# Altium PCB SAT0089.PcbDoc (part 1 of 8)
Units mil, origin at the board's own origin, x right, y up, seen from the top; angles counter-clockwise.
Board outline 4075 x 2715 mil, 6 copper layers (Top Layer, InternalPlane1, MidLayer1, Internal Plane 3, InternalPlane2, Bottom Layer), stack 67.4 mil thick; 538 components, 405 nets, 1716 pads, 1236 vias.
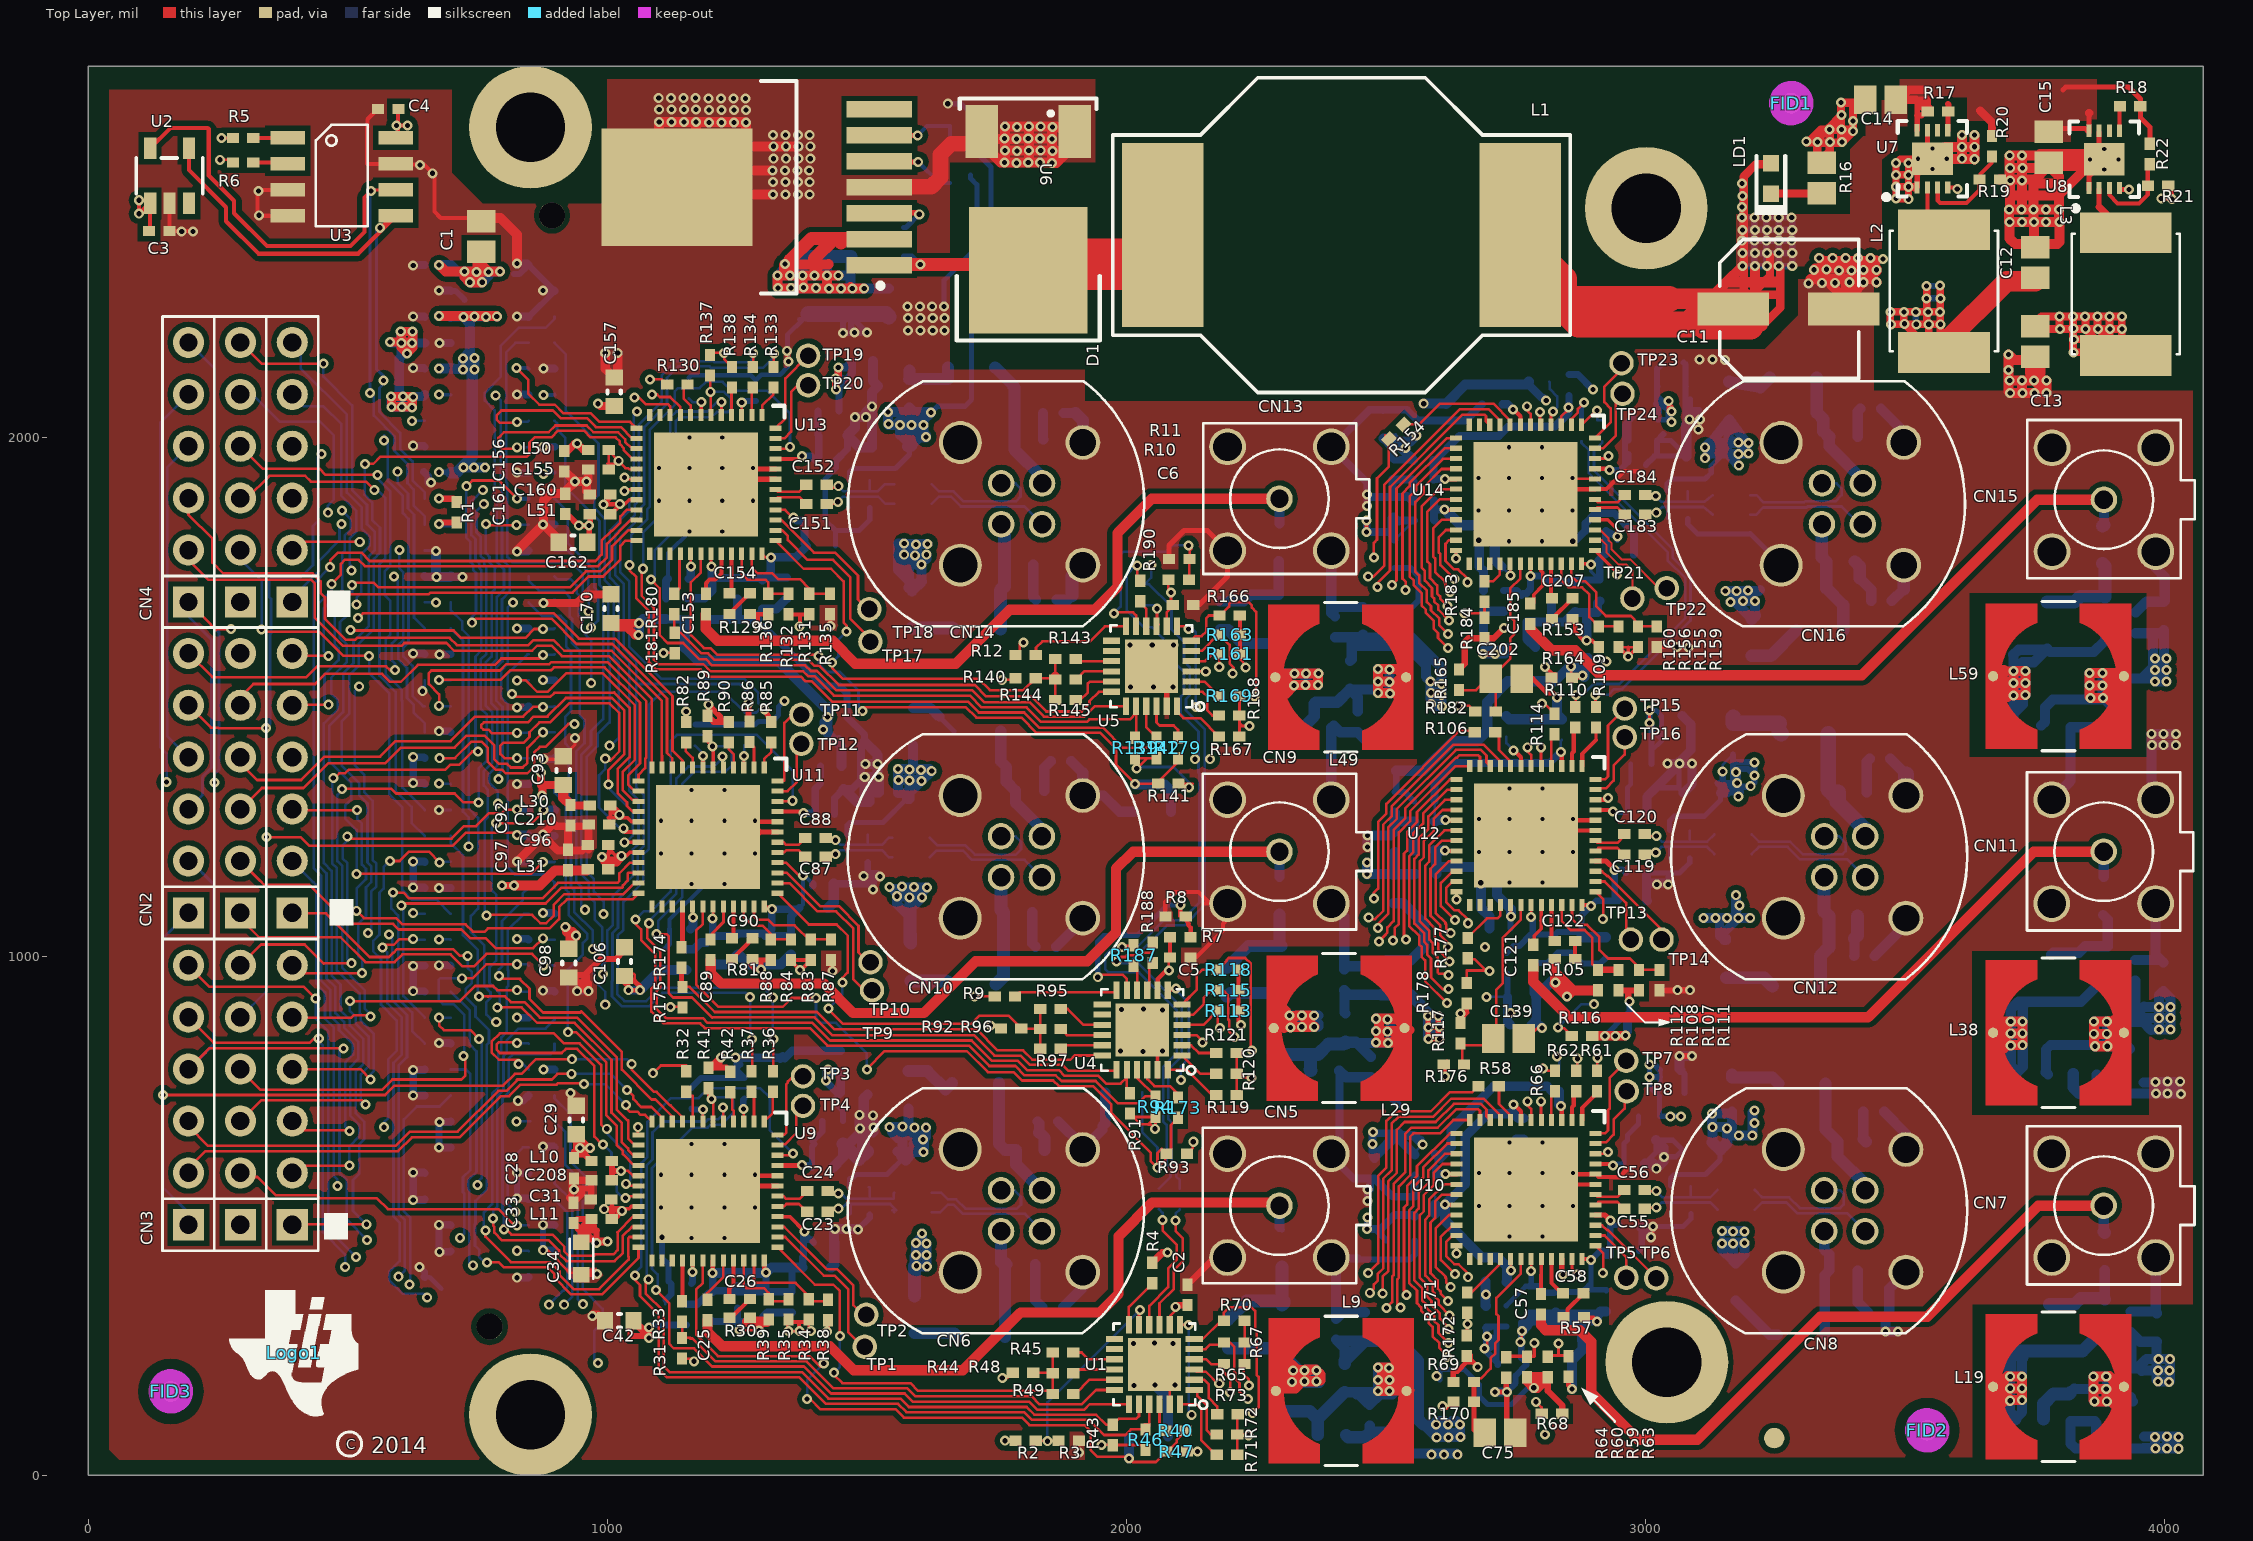
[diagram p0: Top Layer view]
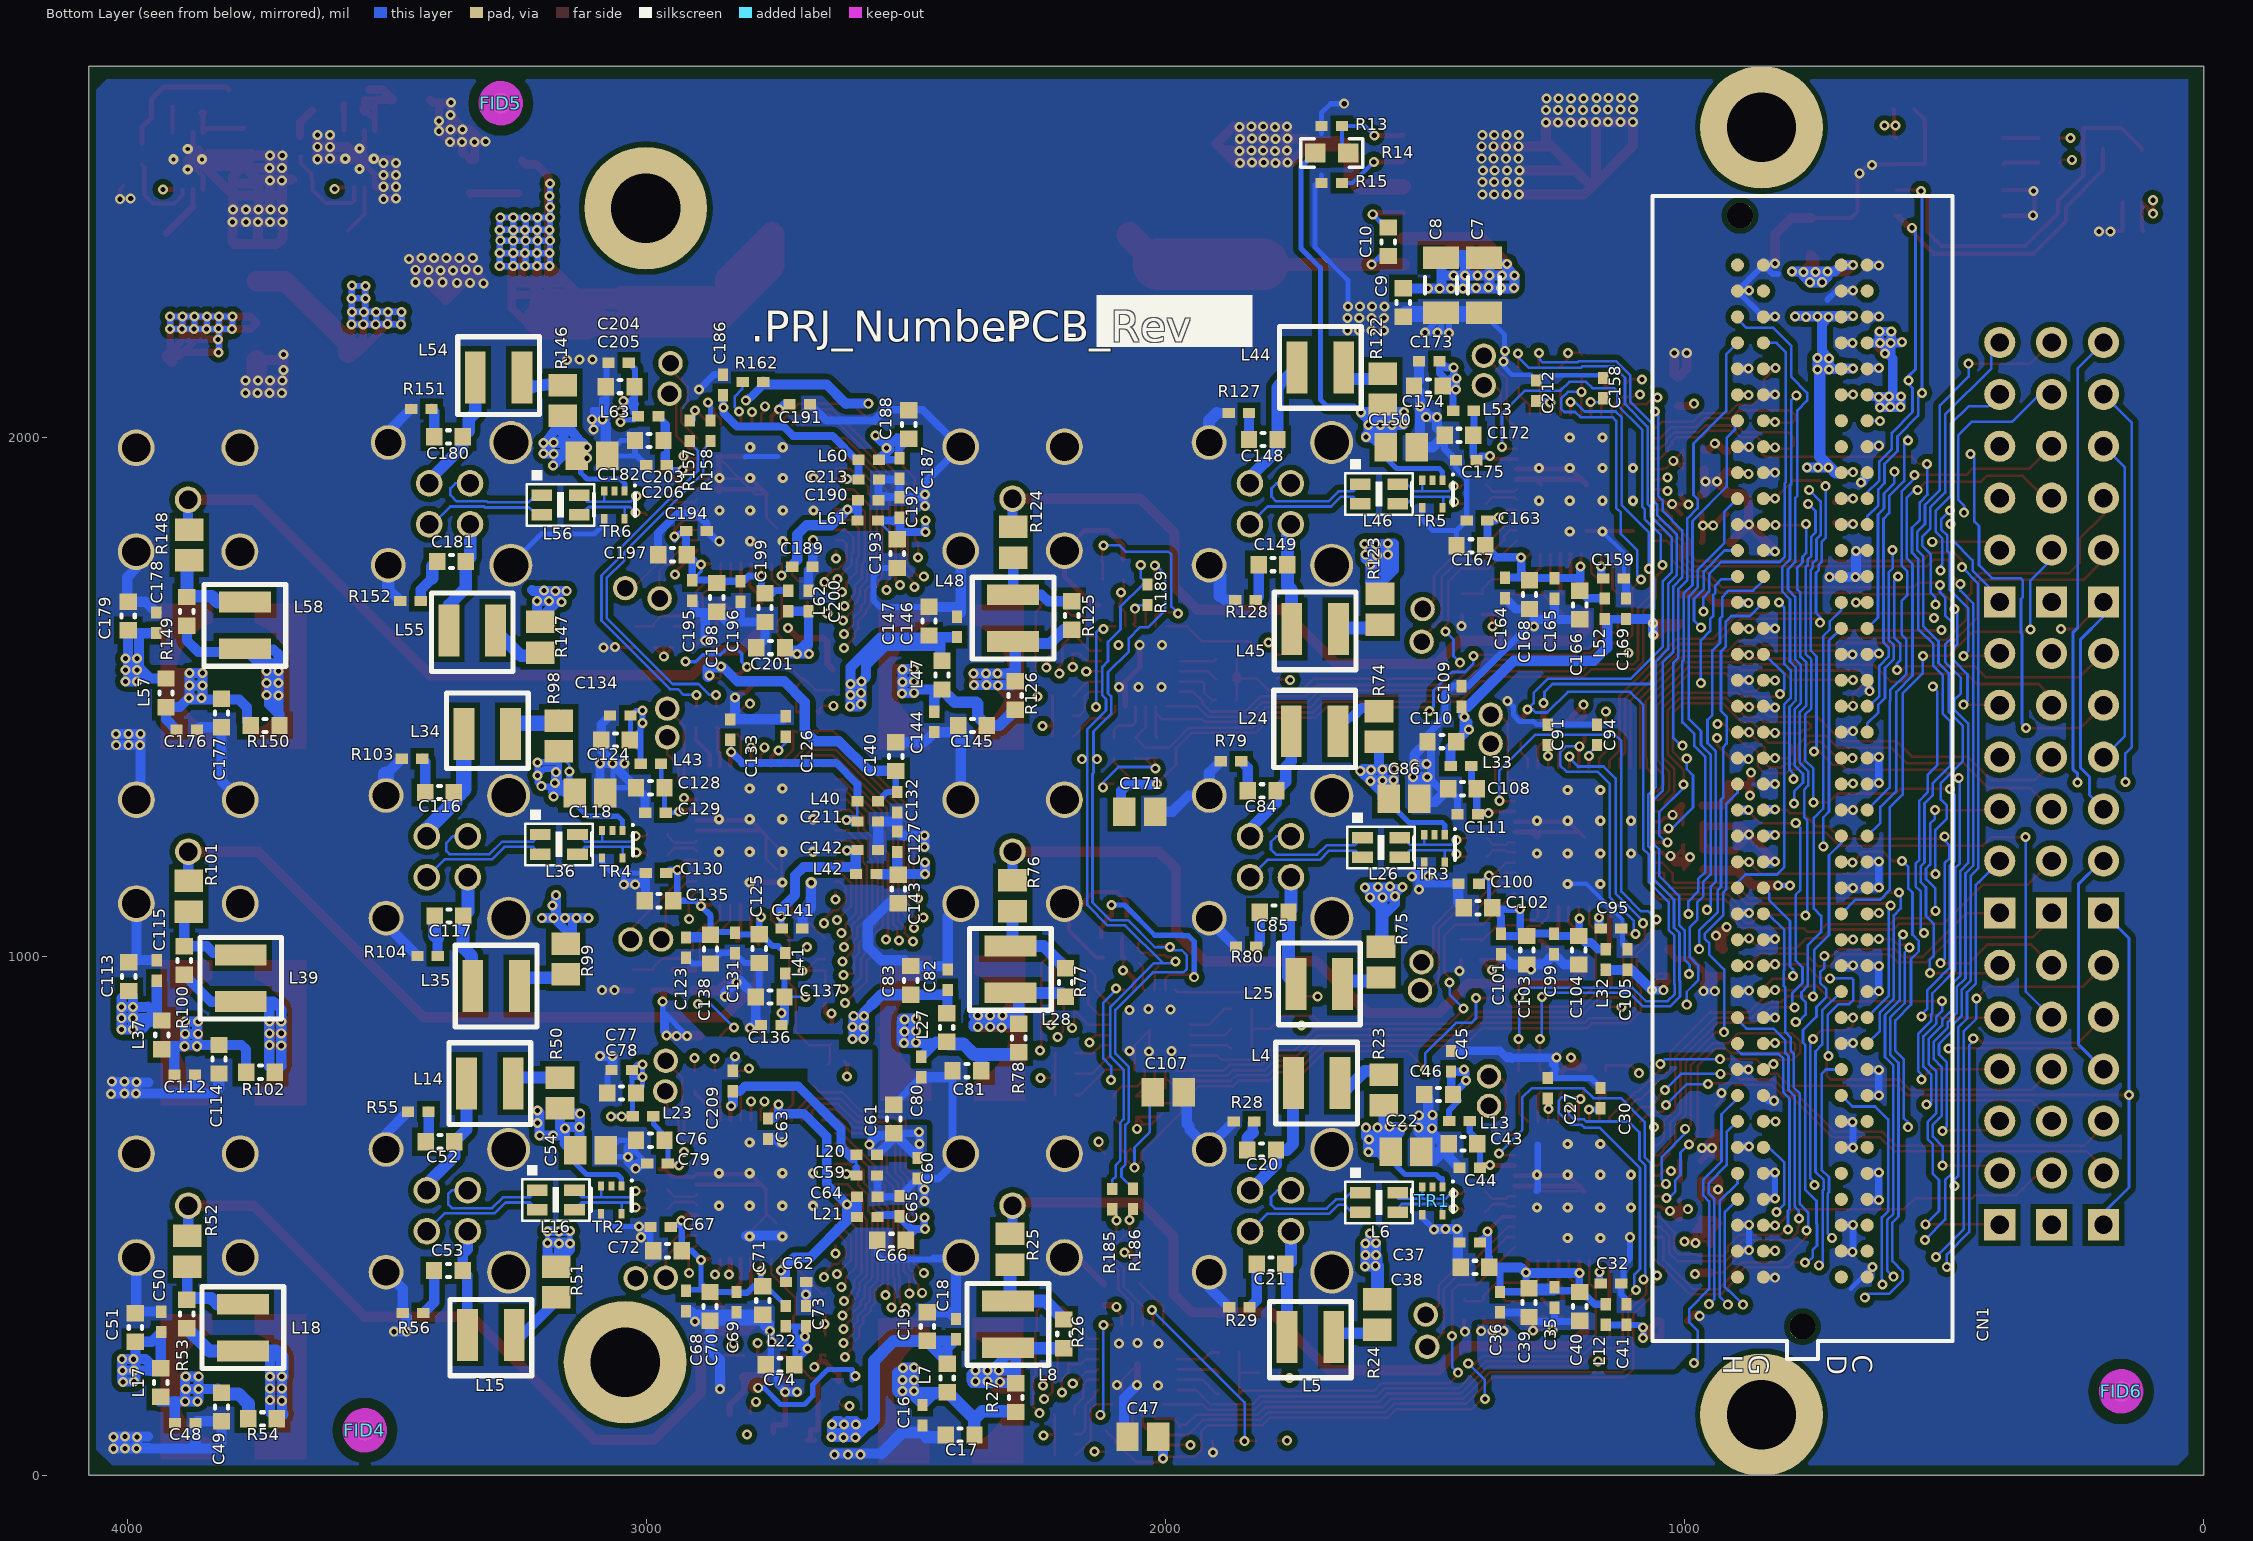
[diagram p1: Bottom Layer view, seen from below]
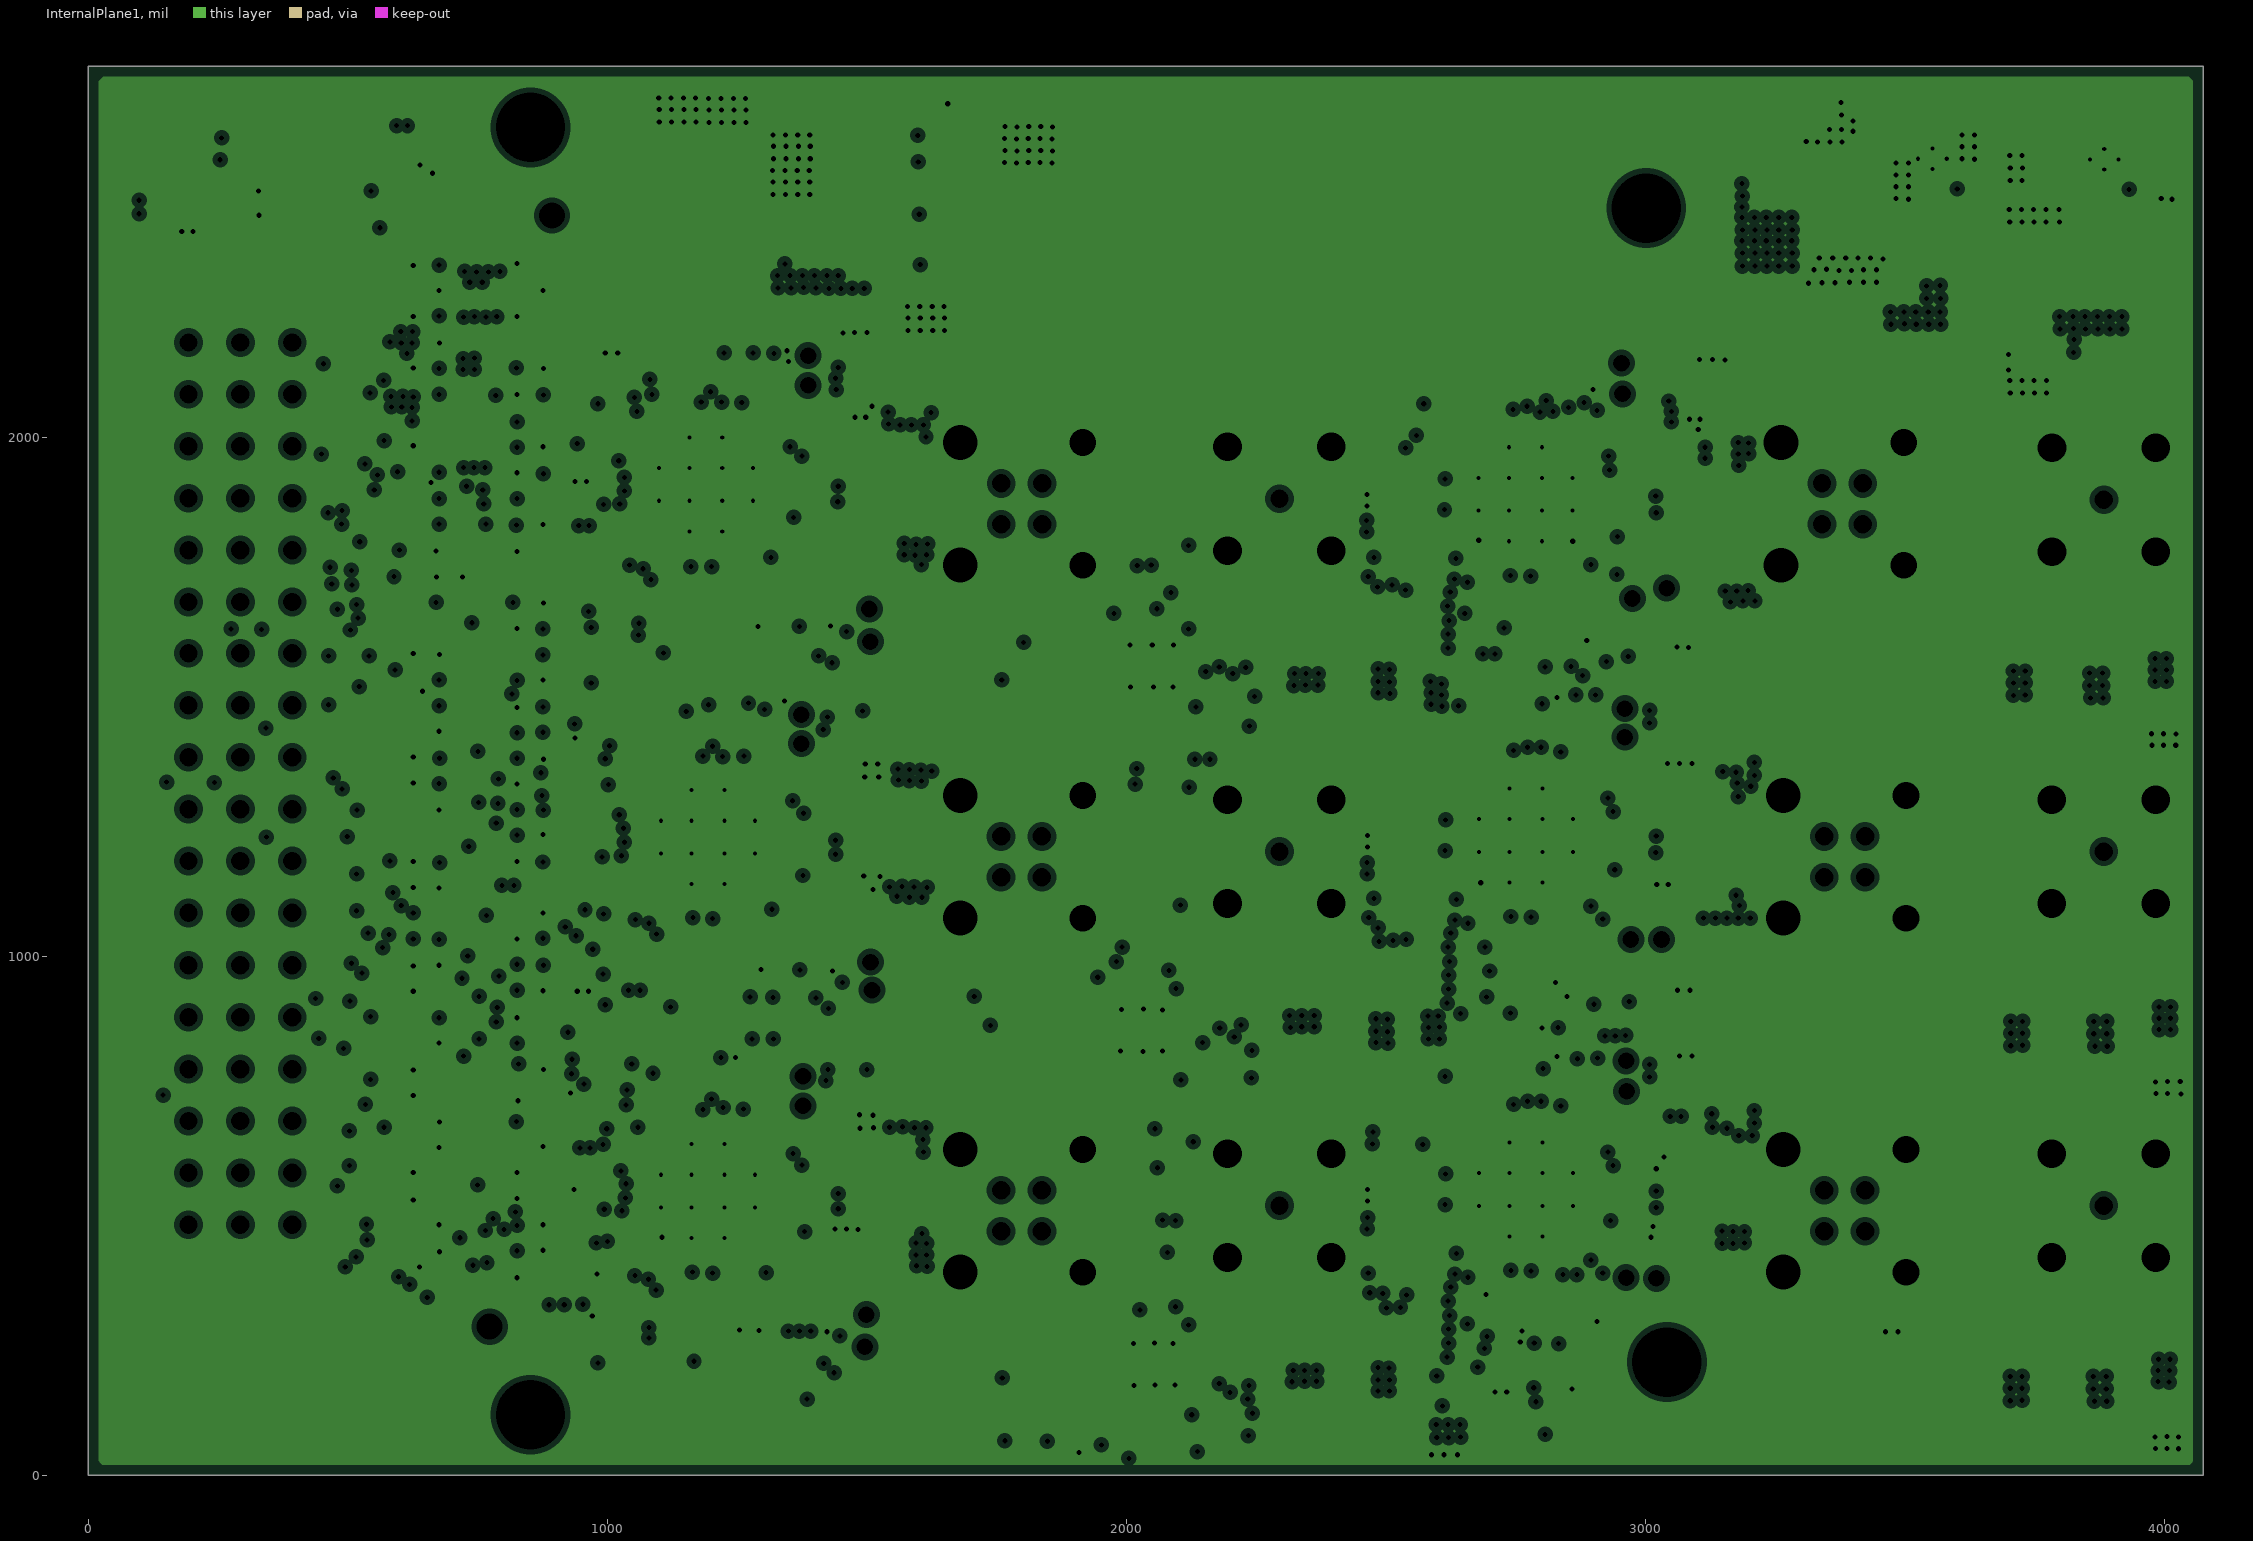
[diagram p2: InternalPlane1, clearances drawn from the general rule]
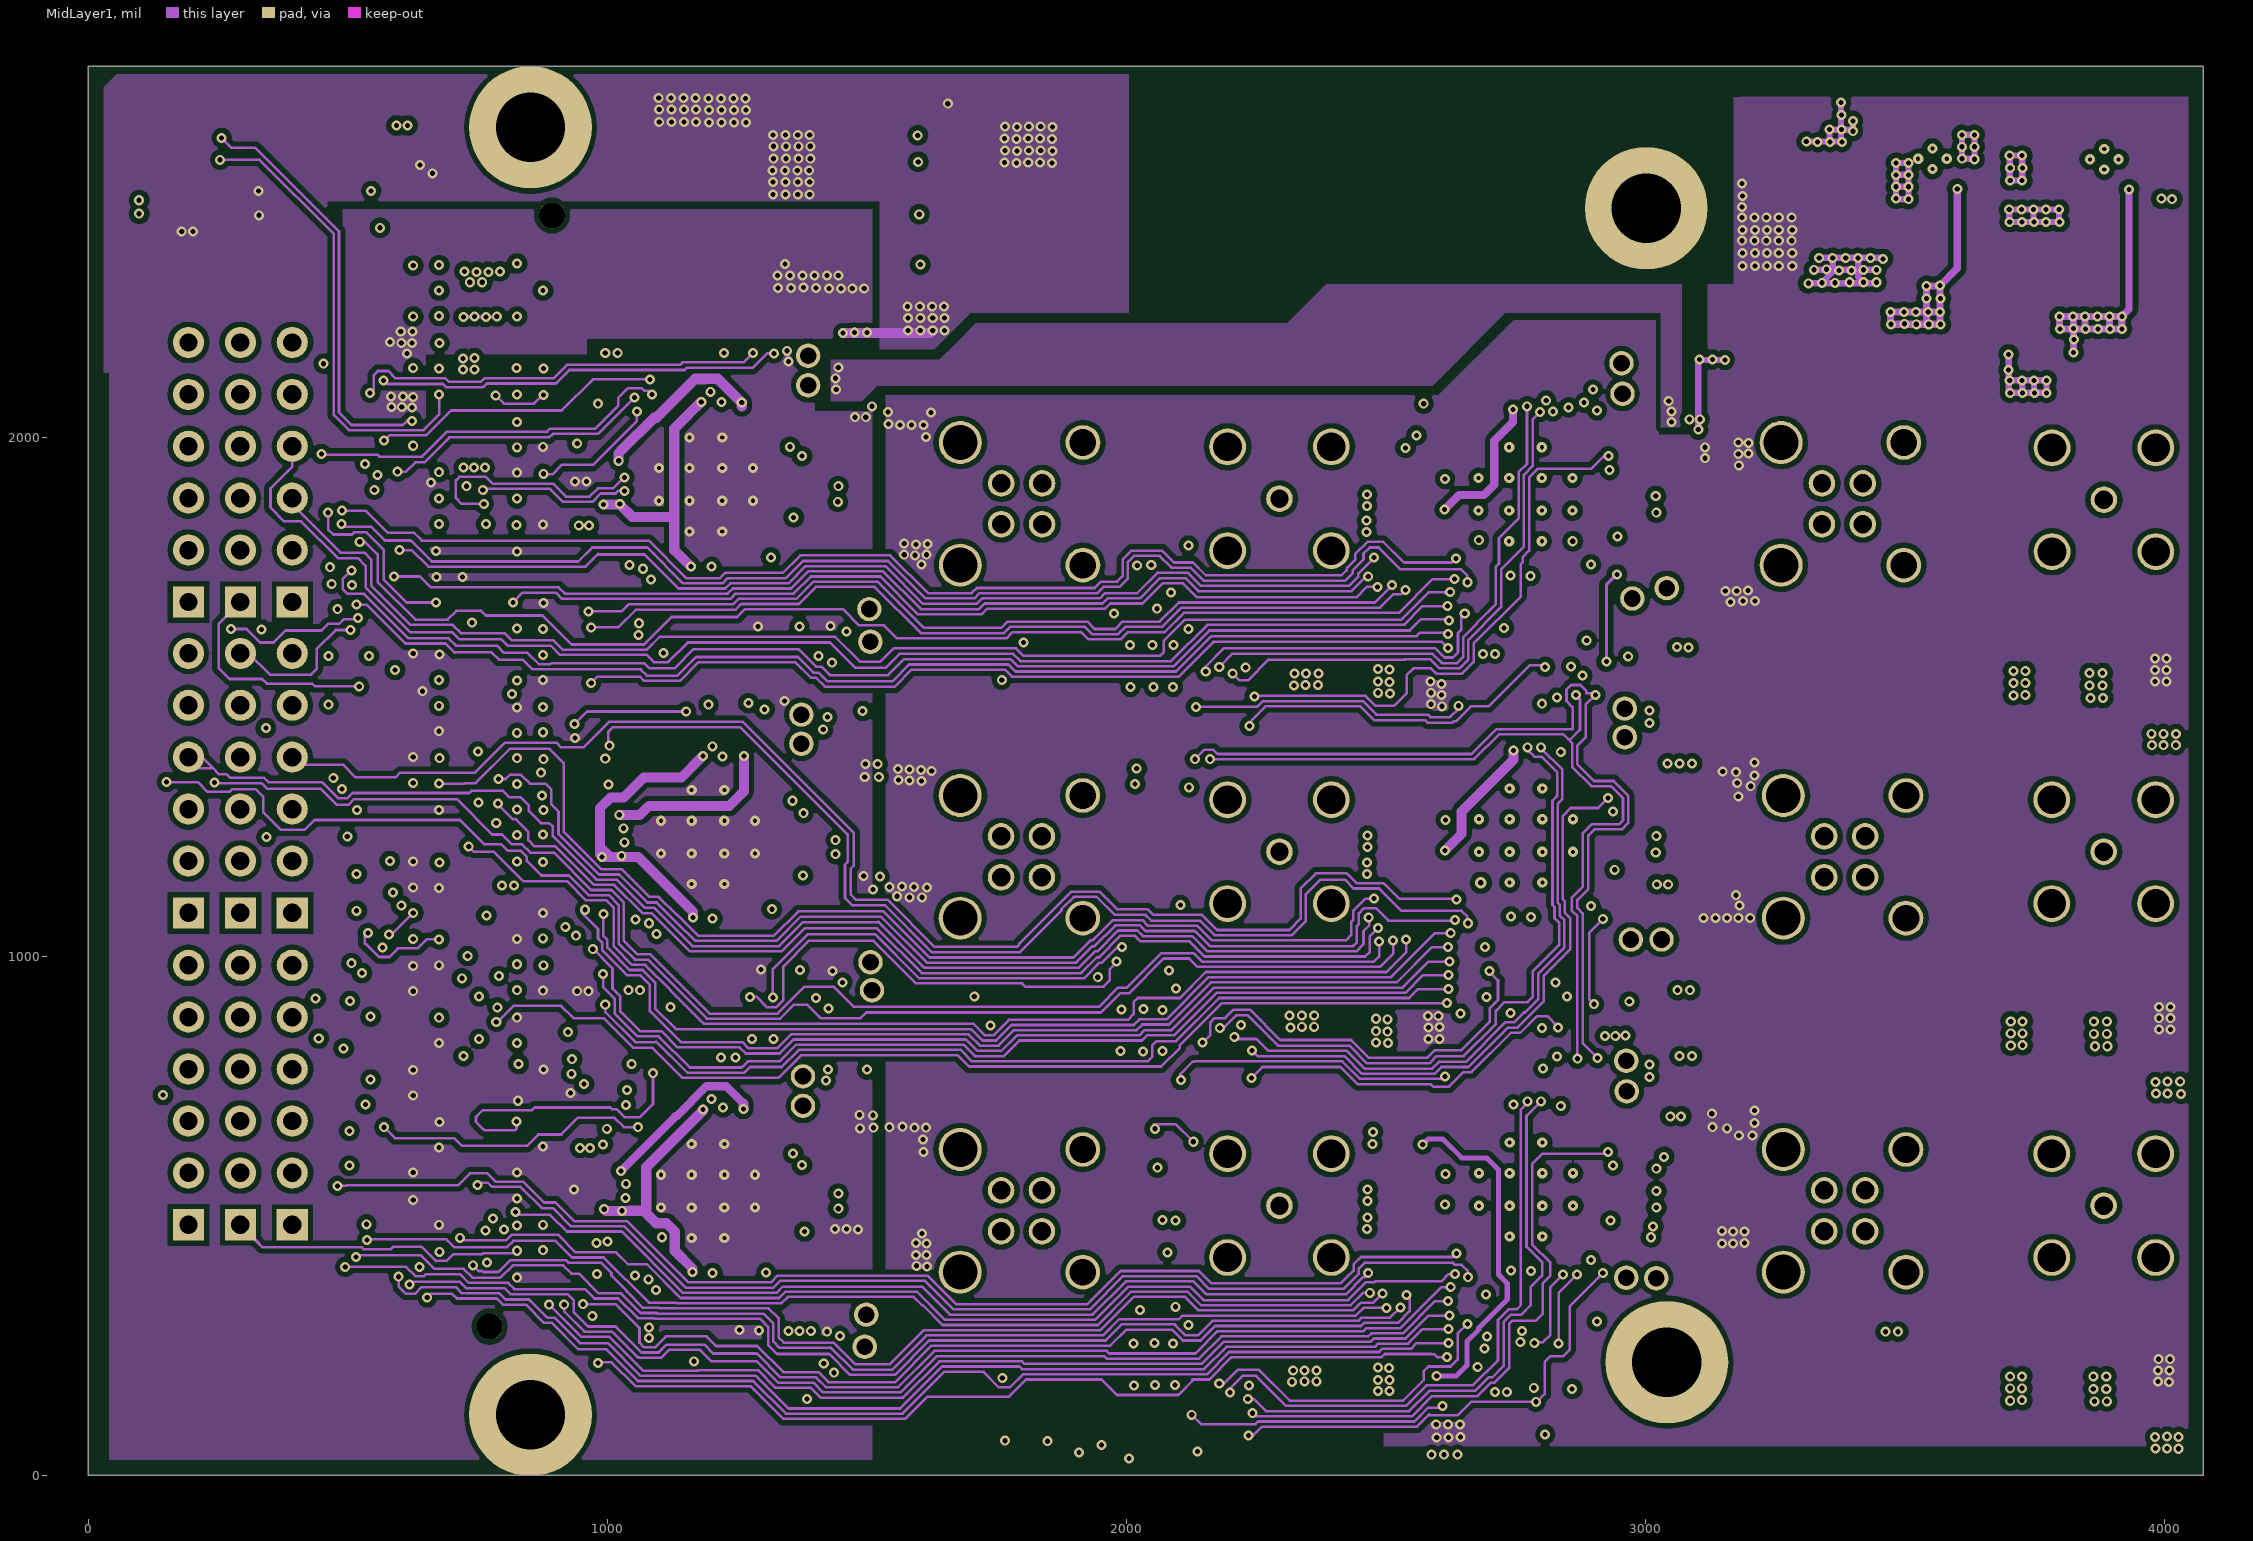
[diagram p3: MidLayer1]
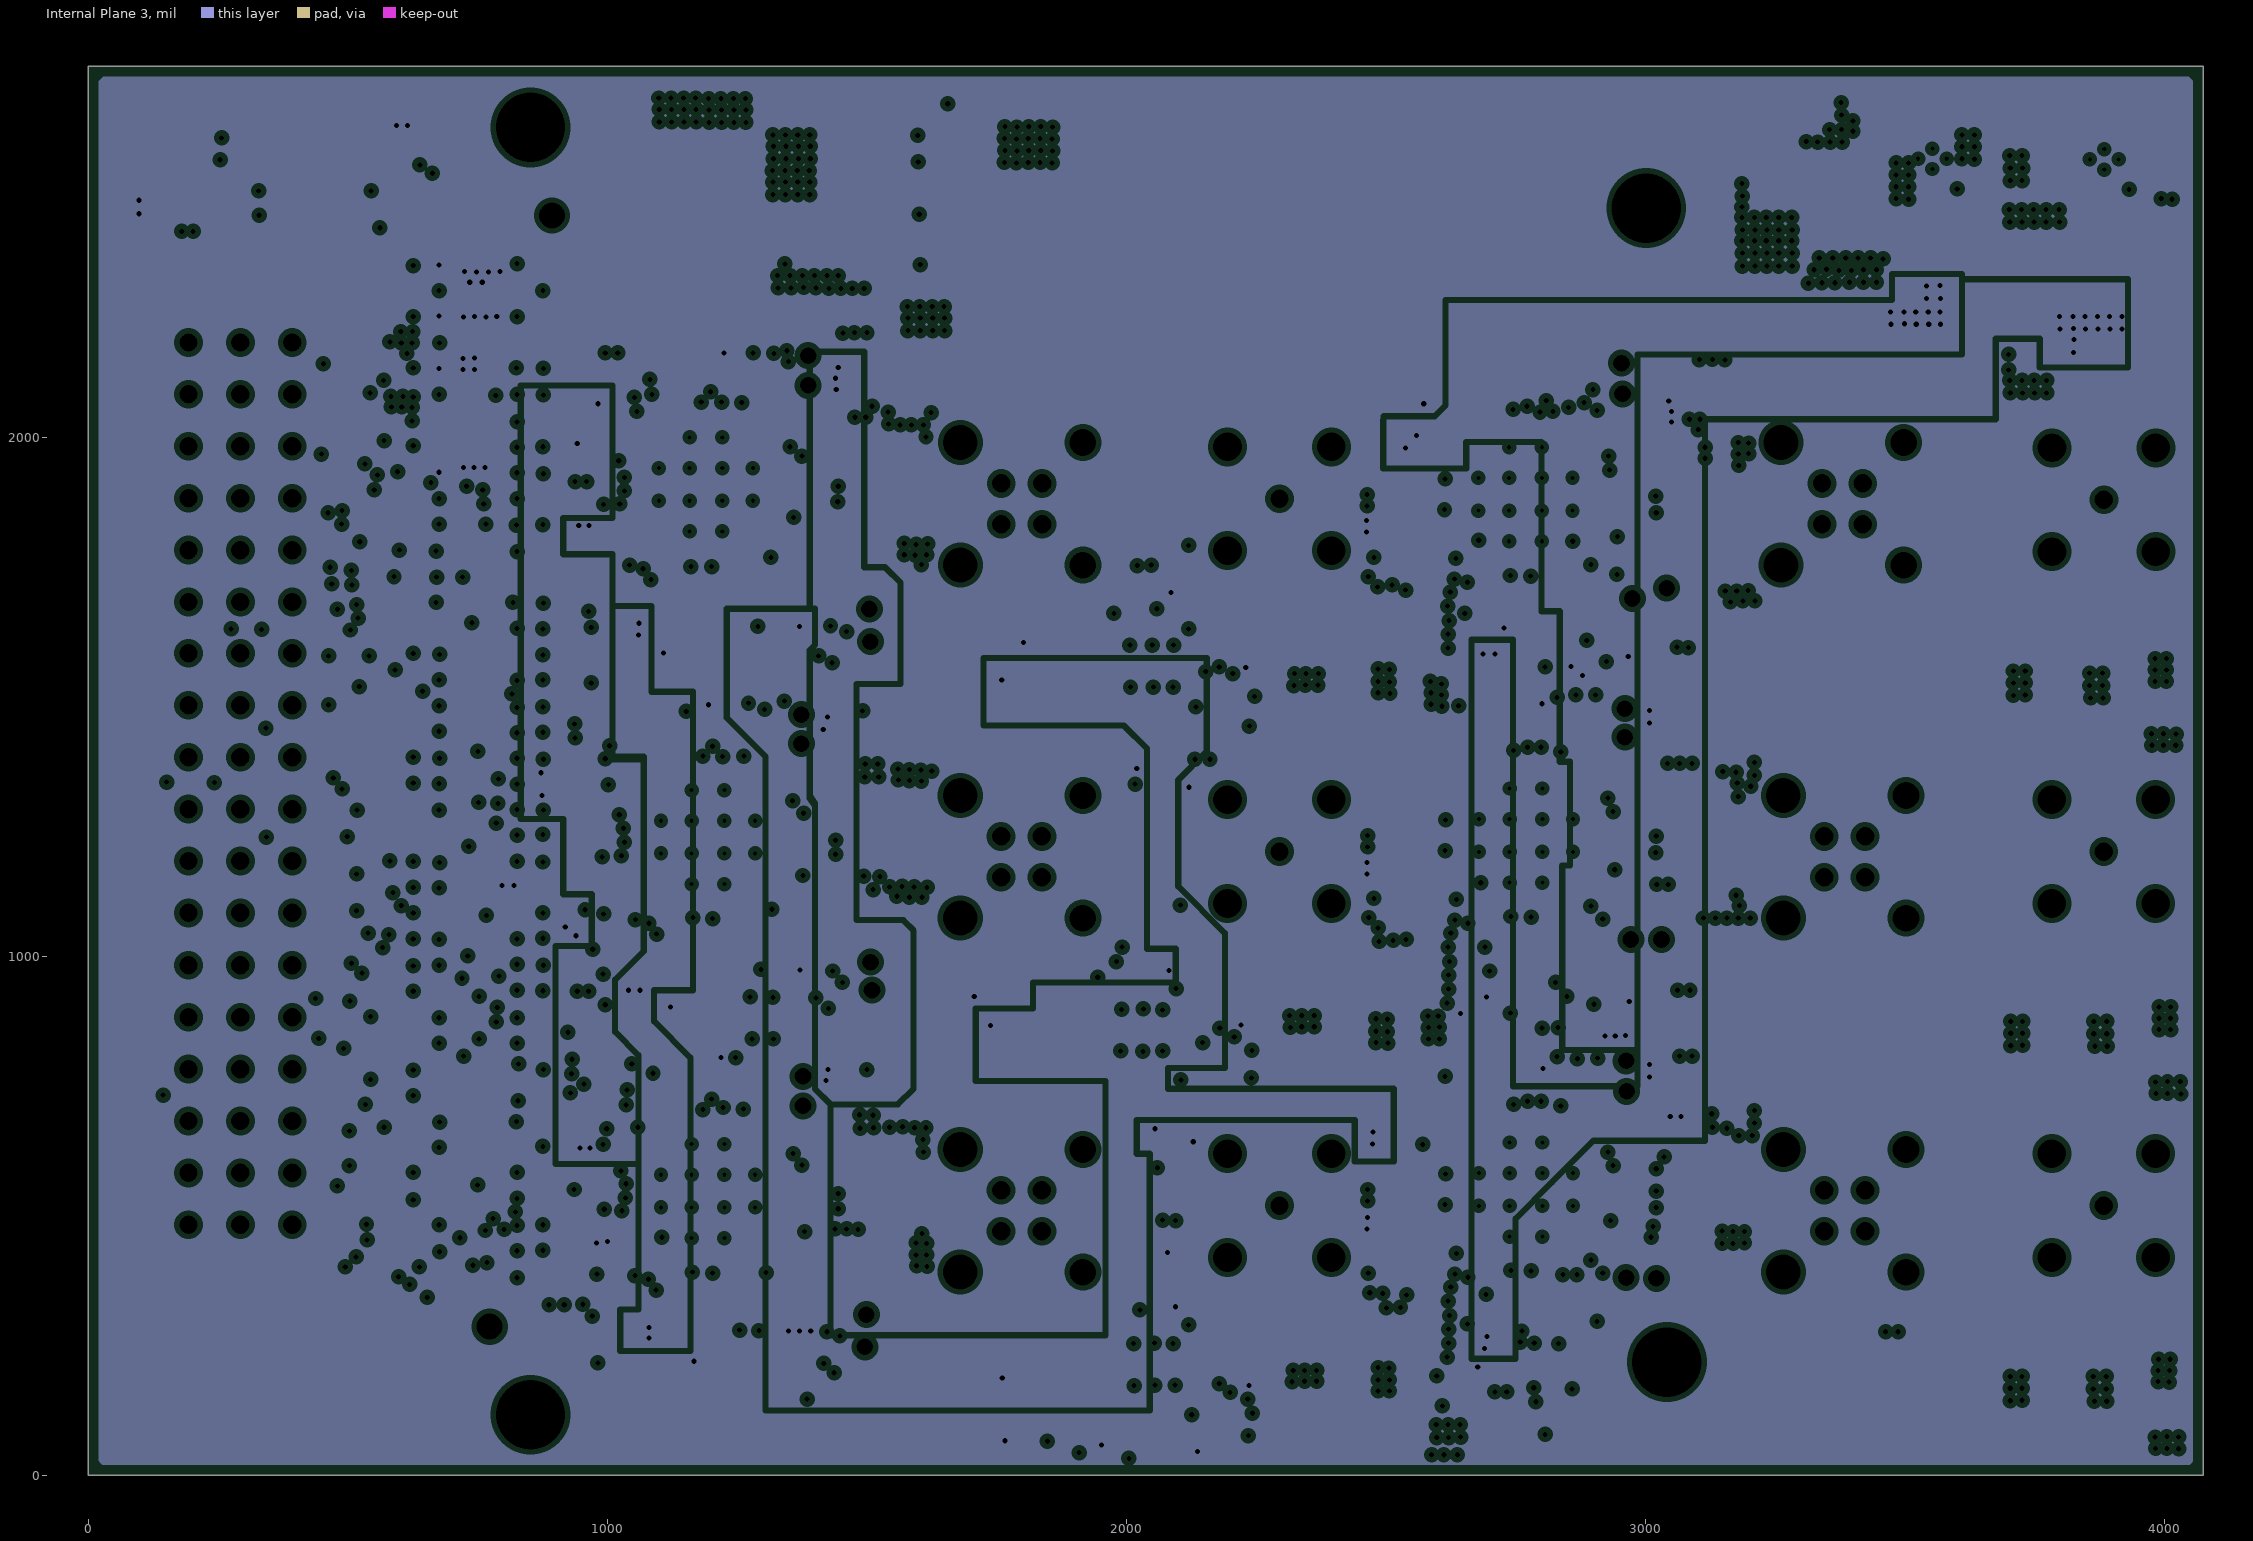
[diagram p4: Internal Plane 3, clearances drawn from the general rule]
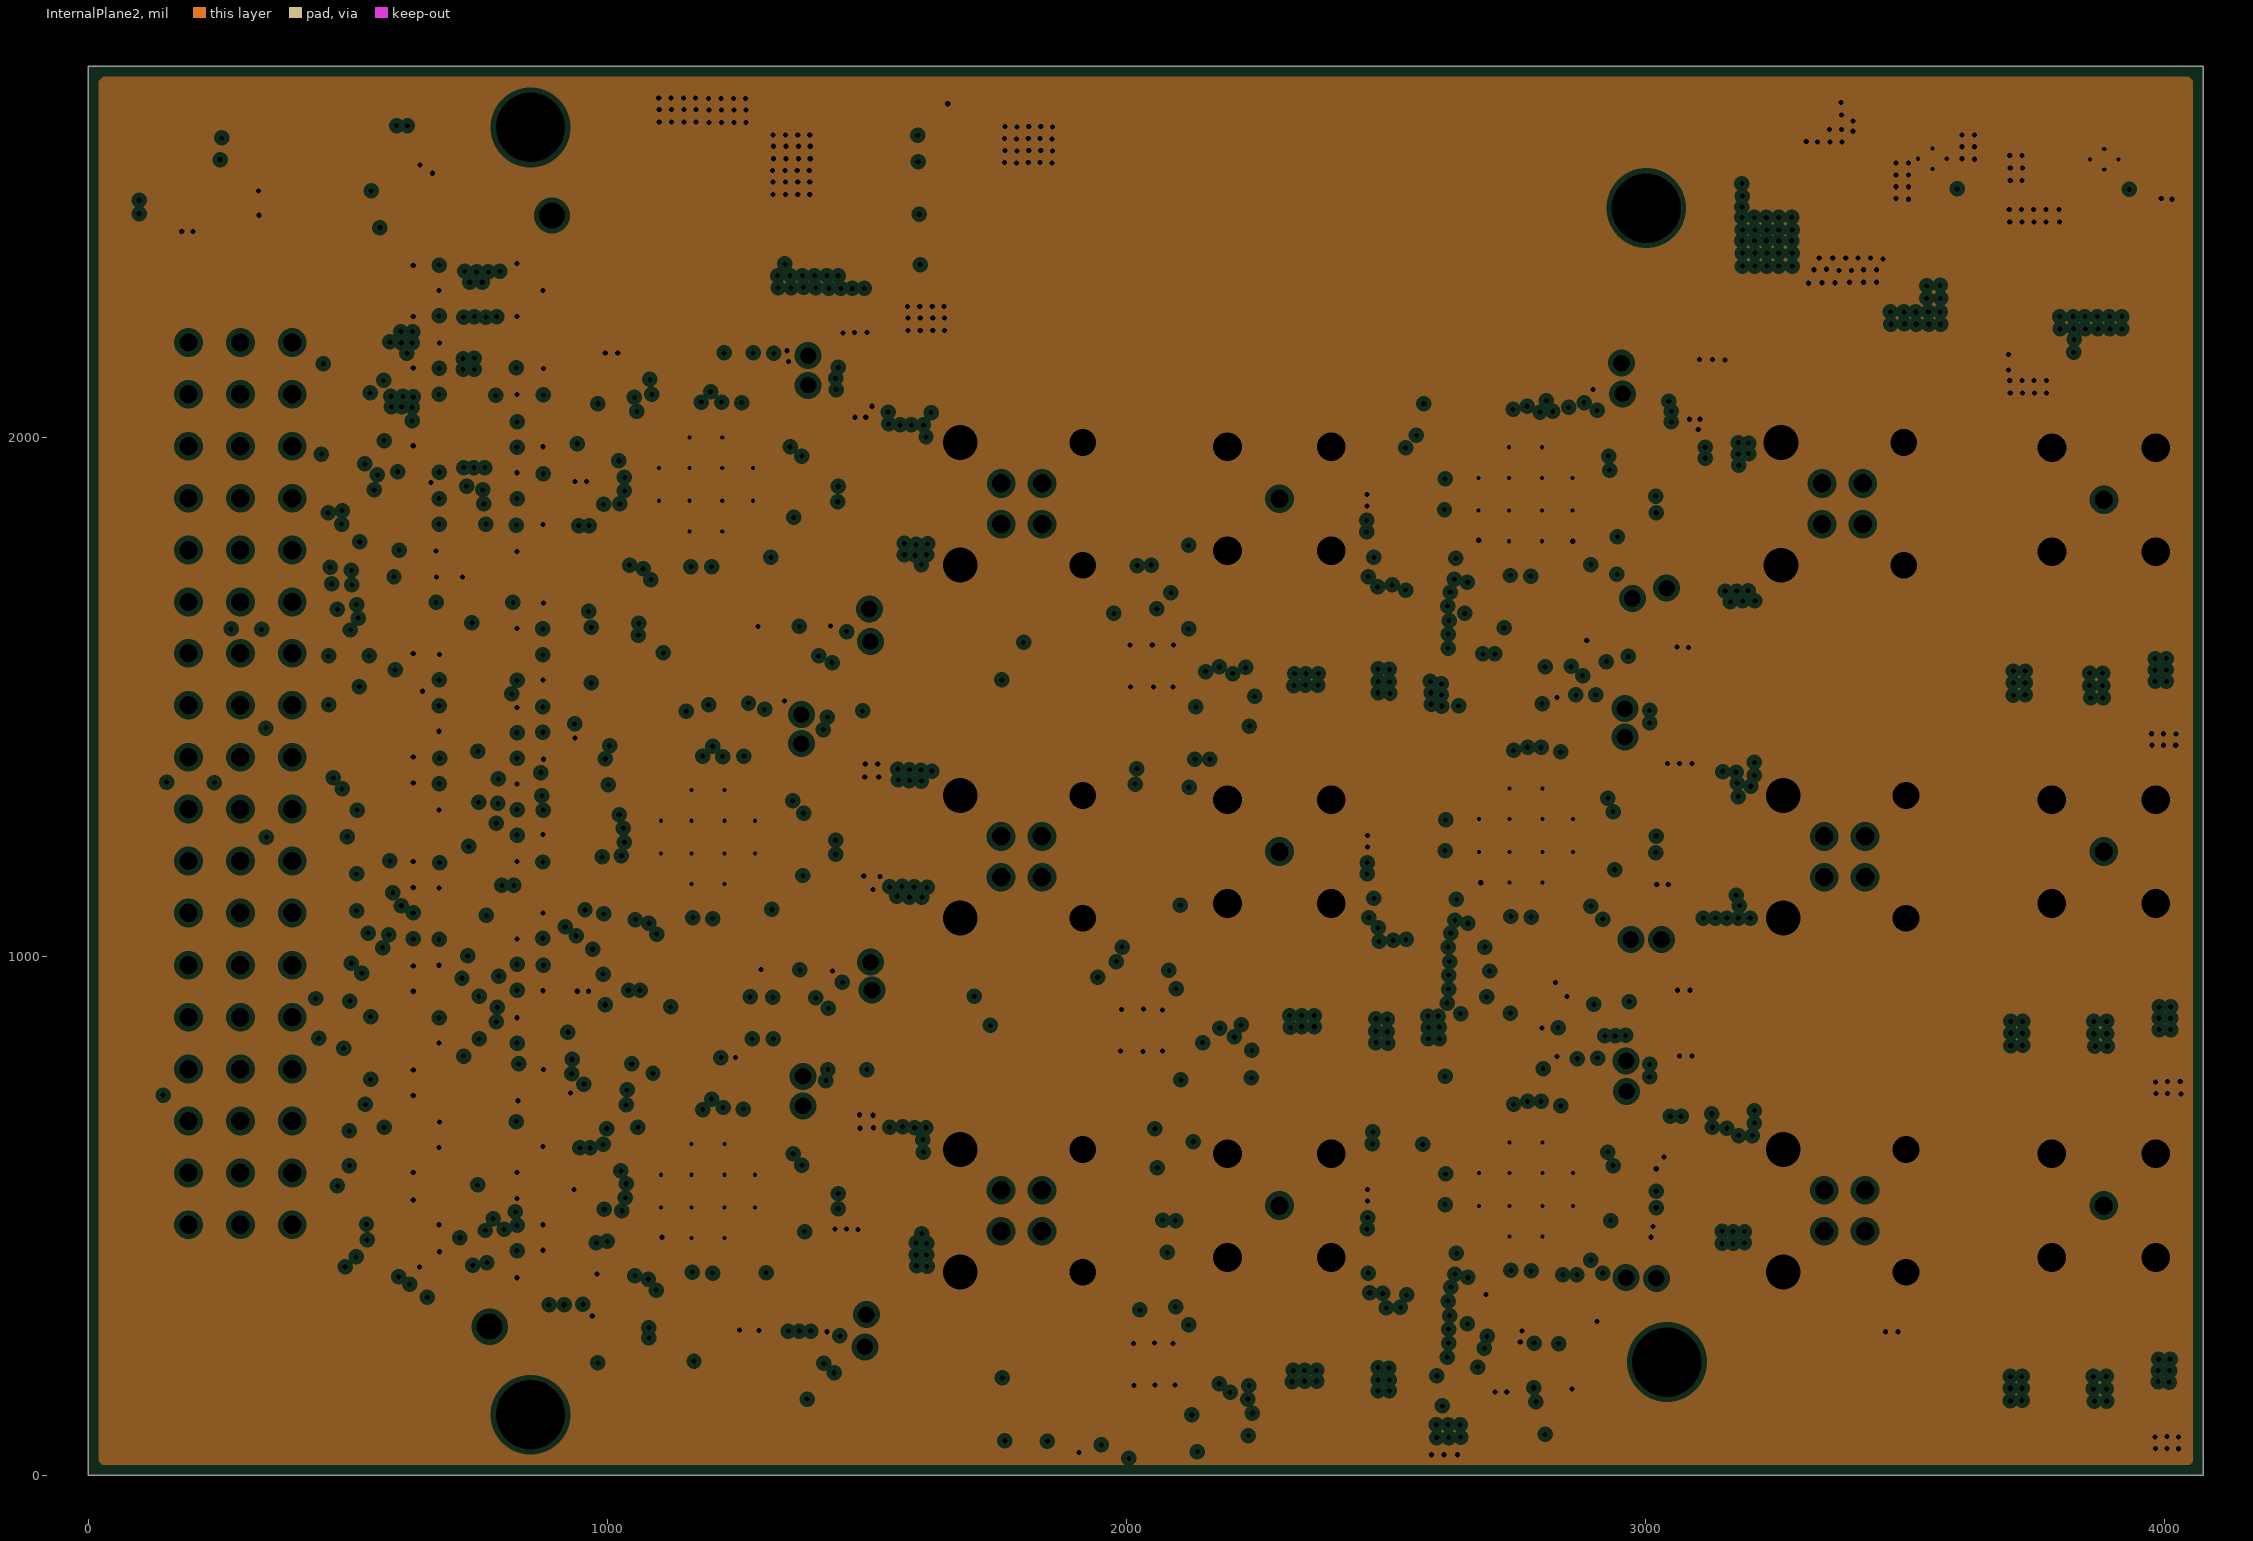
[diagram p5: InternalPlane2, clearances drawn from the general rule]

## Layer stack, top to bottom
Top Layer: signal copper 1.4
Dielectric: prepreg 13, 370HR, Dk 4.8
InternalPlane1: plane copper 1.4, net DGND
Dielectric: core 10, 370HR, Dk 4.8
MidLayer1: signal copper 1.4
Dielectric: prepreg 13, 370HR, Dk 4.8
Internal Plane 3: plane copper 1.4, net (Multiple Nets)
Dielectric: core 10, 370HR, Dk 4.8
InternalPlane2: plane copper 1.4, net DGND
Dielectric: prepreg 13, 370HR, Dk 4.8
Bottom Layer: signal copper 1.4

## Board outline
0,0 0,2715 4075,2715 4075,0

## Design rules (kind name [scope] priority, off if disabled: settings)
AcuteAngle [All] p1: minimum=4.50000000000000E+0001 checktracksonly=FALSE
AssemblyTestPointUsage [All] p1: valid=2
Clearance Clearance_BoardEdge_MountingHoles [OnCopper and InComponentClass('Mounting Holes') vs IsKeepOut] p1: gap=30
Clearance Clearance_BoardEdge_Poly [OnCopper and InPoly vs IsKeepOut] p2: gap=20
Clearance Clearance_BoardEdge [OnCopper and Not InComponentClass('Logo') and not InComponentClass('FiducialMark') and not InRegion(1000,500,4000,800) and Not IsKeepout vs IsKeepOut] p3: gap=20
Clearance Clearance_Poly [InPolygon] p4: gap=10
Clearance [All] p5: gap=5
ComponentClearance ComponentClearance_Shunt [InComponentClass('Header') vs InComponentClass('Shunt')] p1 off: gap=0 collisioncheckmode=3 verticalgap=0 showdistances=FALSE
ComponentClearance ComponentClearance_Logo [InComponentClass('Logo')] p2 off: gap=50 collisioncheckmode=3 verticalgap=10 showdistances=FALSE
ComponentClearance ComponentClearance_ScrewToNut [(HasFootprint('NY PMS 440 0025 PH')) vs (HasFootprint('Keystone_1902C'))] p3 off: gap=5 collisioncheckmode=3 verticalgap=10 showdistances=FALSE
ComponentClearance ComponentClearance_MountingHoles [InComponentClass('Mounting Holes')] p4 off: gap=250 collisioncheckmode=3 verticalgap=100000 showdistances=FALSE
ComponentClearance ComponentClearance_SmallPassives [HasFootprint('0201*') or HasFootprint('0402*') or HasFootprint('0508') or HasFootprint('0603*') or HasFootprint('0612') or HasFootprint('0805*') or HasFootprint('0815*') or HasFootprint('0830*') or HasFootprint('1206*') or HasFootprint('1210*') or HasFootprint('1808*') or HasFootprint('1812*') or HasFootprint('1825*') or HasFootprint('2010*') or HasFootprint('2220*') or HasFootprint('2225*') or HasFootprint('2512*') or HasFootprint('2728*') or HasFootprint('3518*') vs HasFootprint('0201*') or HasFootprint('0402*') or HasFootprint('0508') or HasFootprint('0603*') or HasFootprint('0612') or HasFootprint('0805*') or HasFootprint('0815*') or HasFootprint('0830*') or HasFootprint('1206*') or HasFootprint('1210*') or HasFootprint('1808*') or HasFootprint('1812*') or HasFootprint('1825*') or HasFootprint('2010*') or HasFootprint('2220*') or HasFootprint('2225*') or HasFootprint('2512*') or HasFootprint('2728*') or HasFootprint('3518*')] p5 off: gap=20 collisioncheckmode=3 verticalgap=10 showdistances=FALSE
ComponentClearance ComponentClearance_THtoSMT [IsThruComponent vs IsSMTComponent] p6 off: gap=100 collisioncheckmode=3 verticalgap=30 showdistances=FALSE
ComponentClearance ComponentClearance_THtoTH [IsThruComponent vs IsThruComponent] p7 off: gap=118.11 collisioncheckmode=3 verticalgap=30 showdistances=FALSE
ComponentClearance [All] p8 off: gap=40 collisioncheckmode=3 verticalgap=10 showdistances=FALSE
DiffPairsRouting [All] p1: maxlimit=100 minlimit=10 mostfreqgap=10 maxuncoupledlength=1000
FabricationTestPointUsage TestPointUsage [All] p1: valid=2 allowmultiple=FALSE
FabricationTestpoint Testpoint [All] p1: side=3 testpointundercomponent=TRUE minsize=40 maxsize=100 preferedsize=60 minholesize=0 maxholesize=40 preferedholesize=32 testpointgrid=1 allowsidetop=TRUE allowsidebottom=TRUE usegrid=TRUE gridtolerance=0.01
FanoutControl Fanout_LCC [IsLCC] p1: bgadir=Out bgaviamode=Centered fanoutstyle=Auto fanoutdirection=Alternating viagrid=1 // Fanout_LCC (Default Rule)
FanoutControl Fanout_BGA [IsBGA] p2: bgadir=Out bgaviamode=Centered fanoutstyle=Auto fanoutdirection=Alternating viagrid=1 // Fanout_BGA (Default Rule)
FanoutControl Fanout_Default [All] p4: bgadir=Out bgaviamode=Centered fanoutstyle=Auto fanoutdirection=Alternating viagrid=1 // Fanout_Default (Default Rule)
FanoutControl Fanout_Small [(CompPinCount < 5)] p5: bgadir=Out bgaviamode=Centered fanoutstyle=Auto fanoutdirection=OutThenIn viagrid=1 // Fanout_Small (Default Rule)
HoleSize [All] p1: absolutevalues=TRUE maxlimit=251 minlimit=7.8 maxpercent=80.000 minpercent=20.000
MinimumAnnularRing MinimumAnnularRing_ThermalPadVias [IsVia and InAnyComponent] p1: minimumring=5.91
MinimumAnnularRing [All] p2: minimumring=4.7
MinimumSolderMaskSliver MinimumSolderMaskSliver_Logo [InComponentClass('Logo') vs InComponentClass('Logo')] p1: minsoldermaskwidth=0.7
MinimumSolderMaskSliver [All] p2: minsoldermaskwidth=4
PlaneClearance [All] p1: clearance=10
PlaneConnect [All] p1: planeconnectstyle=Direct reliefexpansion=10 reliefentries=4 reliefconductorwidth=10 reliefairgap=10
PolygonConnect [All] p1: connectstyle=Direct reliefconductorwidth=10 reliefentries=4 polygonreliefangle="90 Angle" airgapwidth=10
RoutingVias ThermalPadVias [IsVia and InAnyComponent] p1: holewidth=7.87 width=19.68 viastyle="Through Hole" minholewidth=7.87 minwidth=19.68 maxholewidth=12.99 maxwidth=23.62
RoutingVias [All] p2: holewidth=16 width=34 viastyle="Through Hole" minholewidth=7.87 minwidth=19 maxholewidth=40 maxwidth=65
SMDToCorner [All] p1: distance=30000
SilkToSilkClearance [All] p1 off: silktosilkclearance=5
SilkscreenOverComponentPads [All] p1: minsilkscreentomaskgap=0.2
SolderMaskExpansion [All] p1: expansion=1
Width [All] p1: maxlimit=100 minlimit=4 preferedwidth=10 midlayer1_minwidth=5 bottomlayer_minwidth=5 minimp=50.000000 maximp=50.000000 favimp=50.000000 checkconnectedcopper=TRUE
13 further rules are at their usual default settings.

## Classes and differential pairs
component class Logo: Logo1
component class Hardware_ANSI-B: FID1 FID2 FID3 FID4 FID5 FID6 Logo1 ZZ2 ZZ3 ZZ4
component class FiducialMark: FID1 FID2 FID3 FID4 FID5 FID6
component class AssemblyNote: ZZ2 ZZ3 ZZ4
component class "CAMERA 1": C16 C17 C18 C19 C20 C21 C22 C23 C24 C25 C26 C27 C28 C29 C30 C31 C32 C33 C34 C35 C36 C37 C38 C39 C40 C41 C42 C43 C44 C45 C46 C47 C208 CN5 CN6 L4 L5 L6 L7 L8 L9 L10 L11 L12 L13 R23 R24 R25 R26 R27 R28 R29 R30 R31 R32 R33 R34 R35 R36 R37 R38 R39 R40 R41 R42 R43 R44 R45 R46 R47 R48 R49 TP1 TP2 TP3 TP4 TR1 U9
component class "CAMERA 2": C48 C49 C50 C51 C52 C53 C54 C55 C56 C57 C58 C59 C60 C61 C62 C63 C64 C65 C66 C67 C68 C69 C70 C71 C72 C73 C74 C75 C76 C77 C78 C79 C209 CN7 CN8 L14 L15 L16 L17 L18 L19 L20 L21 L22 L23 R50 R51 R52 R53 R54 R55 R56 R57 R58 R59 R60 R61 R62 R63 R64 R65 R66 R67 R68 R69 R70 R71 R72 R73 R170 R171 R172 TP5 TP6 TP7 TP8 TR2 U10
component class "CAMERA 3": C80 C81 C82 C83 C84 C85 C86 C87 C88 C89 C90 C91 C92 C93 C94 C95 C96 C97 C98 C99 C100 C101 C102 C103 C104 C105 C106 C107 C108 C109 C110 C111 C210 CN9 CN10 L24 L25 L26 L27 L28 L29 L30 L31 L32 L33 R74 R75 R76 R77 R78 R79 R80 R81 R82 R83 R84 R85 R86 R87 R88 R89 R90 R91 R92 R93 R94 R95 R96 R97 R173 R174 R175 TP9 TP10 TP11 TP12 TR3 U11
component class "CAMERA 4": C112 C113 C114 C115 C116 C117 C118 C119 C120 C121 C122 C123 C124 C125 C126 C127 C128 C129 C130 C131 C132 C133 C134 C135 C136 C137 C138 C139 C140 C141 C142 C143 C211 CN11 CN12 L34 L35 L36 L37 L38 L39 L40 L41 L42 L43 R98 R99 R100 R101 R102 R103 R104 R105 R106 R107 R108 R109 R110 R111 R112 R113 R114 R115 R116 R117 R118 R119 R120 R121 R176 R177 R178 TP13 TP14 TP15 TP16 TR4 U12
component class "CAMERA 5": C144 C145 C146 C147 C148 C149 C150 C151 C152 C153 C154 C155 C156 C157 C158 C159 C160 C161 C162 C163 C164 C165 C166 C167 C168 C169 C170 C171 C172 C173 C174 C175 C212 CN13 CN14 L44 L45 L46 L47 L48 L49 L50 L51 L52 L53 R122 R123 R124 R125 R126 R127 R128 R129 R130 R131 R132 R133 R134 R135 R136 R137 R138 R139 R140 R141 R142 R143 R144 R145 R179 R180 R181 TP17 TP18 TP19 TP20 TR5 U13
component class "CAMERA 6": C176 C177 C178 C179 C180 C181 C182 C183 C184 C185 C186 C187 C188 C189 C190 C191 C192 C193 C194 C195 C196 C197 C198 C199 C200 C201 C202 C203 C204 C205 C206 C207 C213 CN15 CN16 L54 L55 L56 L57 L58 L59 L60 L61 L62 L63 R146 R147 R148 R149 R150 R151 R152 R153 R154 R155 R156 R157 R158 R159 R160 R161 R162 R163 R164 R165 R166 R167 R168 R169 R182 R183 R184 TP21 TP22 TP23 TP24 TR6 U14
component class COMMON: C2 C3 C4 C5 C6 CN2 CN3 CN4 R2 R3 R4 R5 R6 R7 R8 R9 R10 R11 R12 R185 R186 R187 R188 R189 R190 U1 U2 U3 U4 U5
component class MAIN_CONNECTORS: C1 CN1 R1
component class POWER: C7 C8 C9 C10 C11 C12 C13 C14 C15 D1 L1 L2 L3 LD1 R13 R14 R15 R16 R17 R18 R19 R20 R21 R22 U6 U7 U8

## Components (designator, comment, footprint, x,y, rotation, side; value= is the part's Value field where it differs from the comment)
C1 "GRM21BR71A106KE51L" 0805L 757,2387 r90 top
C2 "GRM155R71C104KA88D" 0402L 2118,348 r270 top
C3 "GRM155R71C104KA88D" 0402L 136.85,2397.72 r0 top
C4 "GRM155R71C104KA88D" 0402L 578,2633 r180 top
C5 "GRM155R71C104KA88D" 0402L 2104,998 r180 top
C6 "GRM155R71C104KA88D" 0402L 2109,1677 r180 top
C7 "GRM31CR71E106KA12L" 1206L 1386.85,2293.39 r270 bottom
C8 "GRM31CR71E106KA12L" 1206L 1469.53,2293.39 r270 bottom
C9 "GCM188R71H104KA57B" 0603L 1542.36,2259.92 r270 bottom
C10 "GRM188R71H103KA01D" 0603L 1571,2377 r270 bottom
C11 "APXC100ARA820MF60G" CAPSMT_62_F60 3275,2247 r0 top
C12 "GRM21BR71A106KE51L" 0805L 3751,2337 r90 top
C13 "GRM21BR71A106KE51L" 0805L 3751,2185 r270 top
C14 "GRM21BR71A106KE51L" 0805L 3453.06,2650.72 r180 top
C15 "GRM21BR71A106KE51L" 0805L 3777,2559 r270 top
C16 "GRM155R71C104KA88D" 0402L 2468.5,116 r270 bottom
C17 "GRM188R61E475KE11D" 0603L 2396,78 r0 bottom
C18 "GRM155R71C104KA88D" 0402L 2404,282 r90 bottom
C19 "GRM188R61E475KE11D" 0603L 2459,287 r90 bottom
C20 "GRM188R72A104KA35D" 0603L 1815,627 r0 bottom
C21 "GRM188R72A104KA35D" 0603L 1797,407 r0 bottom
C22 "GRM21BR61C106KE15L" 0805L 1537,624 r180 bottom
C23 "GRM155R71C104KA88D" 0402L 1405,508 r0 top
C24 "GRM155R71C104KA88D" 0402L 1405,548 r0 top
C25 "GRM155R71C104KA88D" 0402L 1193,319 r270 top
C26 "GRM155R71C473KA01D" 0402L 1255,340 r180 top
C27 "GRM155R71C104KA88D" 0402L 1264,746 r90 bottom
C28 "GRM155R71C104KA88D" 0402L 936,592 r270 top
C29 "GRM188R61E475KE11D" 0603L 940,685 r90 top
C30 "GRM155R71C104KA88D" 0402L 1162,727 r90 bottom
C31 "GRM155R71C104KA88D" 0402L 988,532 r180 top
C32 "GRM155R71C104KA88D" 0402L 1142,370 r180 bottom
C33 "GRM155R71C104KA88D" 0402L 935,506 r90 top
C34 "GRM188R61E475KE11D" 0603#1 950,418 r270 top
C35 "GRM155R71C104KA88D" 0402L 1251,343 r270 bottom
C36 "GRM155R71C104KA88D" 0402L 1356,334 r270 bottom
C37 "GRM155R71C104KA88D" 0402L 1414,449 r0 bottom
C38 "GRM188R61E475KE11D" 0603L 1404,401 r0 bottom
C39 "GRM188R61E475KE11D" 0603L 1300,333 r270 bottom
C40 "GRM188R61E475KE11D" 0603L 1202,326 r270 bottom
C41 "GRM155R71C104KA88D" 0402L 1112,310 r90 bottom
C42 "GRM188R61E475KE11D" 0603L 1023,298 r180 top
C43 "GRM188R61E475KE11D" 0603L 1427,639 r0 bottom
C44 "GRM155R71C104KA88D" 0402L 1414,593 r0 bottom
C45 "GRM155R71C104KA88D" 0402L 1450,798 r90 bottom
C46 "GRM188R61E475KE11D" 0603L 1474,734 r0 bottom
C47 "JMK212BJ226KG-T" 0805L 2044,75 r0 bottom
C48 "GRM155R71C104KA88D" 0402L 3889,101 r180 bottom
C49 "GRM188R61E475KE11D" 0603L 3819,132 r270 bottom
C50 "GRM155R71C104KA88D" 0402L 3935,296 r90 bottom
C51 "GRM188R61E475KE11D" 0603L 3985,285 r90 bottom
C52 "GRM188R72A104KA35D" 0603L 3398,643 r0 bottom
C53 "GRM188R72A104KA35D" 0603L 3382,395 r0 bottom
C54 "GRM21BR61C106KE15L" 0805L 3108,627 r180 bottom
C55 "GRM155R71C104KA88D" 0402L 2979,514 r0 top
C56 "GRM155R71C104KA88D" 0402L 2979,550 r0 top
C57 "GRM155R71C104KA88D" 0402L 2799,330 r270 top
C58 "GRM155R71C473KA01D" 0402L 2861,351 r180 top
C59 "GRM155R71C104KA88D" 0402L 2576,578 r180 bottom
C60 "GRM155R71C104KA88D" 0402L 2478,592 r270 bottom
C61 "GRM188R61E475KE11D" 0603L 2524,687 r90 bottom
C62 "GRM155R71C104KA88D" 0402L 2712,373 r180 bottom
C63 "GRM155R71C104KA88D" 0402L 2766,668 r270 bottom
C64 "GRM155R71C104KA88D" 0402L 2575,537 r180 bottom
C65 "GRM155R71C104KA88D" 0402L 2513,519 r90 bottom
C66 "GRM188R61E475KE11D" 0603L 2528,453 r0 bottom
C67 "GRM155R71C104KA88D" 0402L 2973,479 r0 bottom
C68 "GRM155R71C104KA88D" 0402L 2924,336 r270 bottom
C69 "GRM155R71C104KA88D" 0402L 2827,334 r270 bottom
C70 "GRM188R61E475KE11D" 0603L 2878,326 r270 bottom
C71 "GRM188R61E475KE11D" 0603L 2776,337 r270 bottom
C72 "GRM188R61E475KE11D" 0603L 2960,433 r0 bottom
C73 "GRM155R71C104KA88D" 0402L 2693,307 r90 bottom
C74 "GRM188R61E475KE11D" 0603L 2743,213 r0 bottom
C75 "JMK212BJ226KG-T" 0805L 2720,82 r0 top
C76 "GRM188R61E475KE11D" 0603L 2993,646 r0 bottom
C77 "GRM155R71C104KA88D" 0402L 3048,781 r0 bottom
C78 "GRM188R61E475KE11D" 0603L 3048,737 r0 bottom
C79 "GRM155R71C104KA88D" 0402L 2979,601 r0 bottom
C80 "GRM155R71C104KA88D" 0402L 2471,787 r270 bottom
C81 "GRM188R61E475KE11D" 0603L 2383,780 r0 bottom
C82 "GRM155R71C104KA88D" 0402L 2420,955 r90 bottom
C83 "GRM188R61E475KE11D" 0603L 2491,954 r90 bottom
C84 "GRM188R72A104KA35D" 0603L 1814,1319 r0 bottom
C85 "GRM188R72A104KA35D" 0603L 1791,1085 r0 bottom
C86 "GRM21BR61C106KE15L" 0805L 1541,1304 r180 bottom
C87 "GRM155R71C104KA88D" 0402L 1401,1192 r0 top
C88 "GRM155R71C104KA88D" 0402L 1401,1228 r0 top
C89 "GRM155R71C104KA88D" 0402L 1199,1013 r270 top
C90 "GRM155R71C473KA01D" 0402L 1260,1035 r180 top
C91 "GRM155R71C104KA88D" 0402L 1264,1427 r90 bottom
C92 "GRM155R71C104KA88D" 0402L 929,1272 r270 top
C93 "GRM188R61E475KE11D" 0603L 915,1358 r90 top
C94 "GRM155R71C104KA88D" 0402L 1169,1427 r90 bottom
C95 "GRM155R71C104KA88D" 0402L 1142,1054 r180 bottom
C96 "GRM155R71C104KA88D" 0402L 982,1215 r180 top
C97 "GRM155R71C104KA88D" 0402L 924,1186 r90 top
C98 "GRM188R61E475KE11D" 0603L 926,987 r270 top
C99 "GRM155R71C104KA88D" 0402L 1252,1024 r270 bottom
C100 "GRM155R71C104KA88D" 0402L 1416,1140 r0 bottom
C101 "GRM155R71C104KA88D" 0402L 1354,1024 r270 bottom
C102 "GRM188R61E475KE11D" 0603L 1398,1094 r0 bottom
C103 "GRM188R61E475KE11D" 0603L 1304,1012 r270 bottom
C104 "GRM188R61E475KE11D" 0603L 1204,1012 r270 bottom
C105 "GRM155R71C104KA88D" 0402L 1110,994 r90 bottom
C106 "GRM188R61E475KE11D" 0603L 1033,990 r90 top
C107 "JMK212BJ226KG-T" 0805L 1995,738 r180 bottom
C108 "GRM188R61E475KE11D" 0603L 1428,1323 r0 bottom
C109 "GRM155R71C104KA88D" 0402L 1430,1501 r90 bottom
C110 "GRM188R61E475KE11D" 0603L 1468,1414 r0 bottom
C111 "GRM155R71C104KA88D" 0402L 1418,1274 r0 bottom
C112 "GRM155R71C104KA88D" 0402L 3890,772 r180 bottom
C113 "GRM188R61E475KE11D" 0603L 3998,961 r90 bottom
C114 "GRM188R61E475KE11D" 0603L 3824,802 r270 bottom
C115 "GRM155R71C104KA88D" 0402L 3944,973 r90 bottom
C116 "GRM188R72A104KA35D" 0603L 3399,1316 r0 bottom
C117 "GRM188R72A104KA35D" 0603L 3381,1078 r0 bottom
C118 "GRM21BR61C106KE15L" 0805L 3109,1315 r180 bottom
C119 "GRM155R71C104KA88D" 0402L 2979,1196 r0 top
C120 "GRM155R71C104KA88D" 0402L 2979,1236 r0 top
C121 "GRM155R71C104KA88D" 0402L 2784,1003 r270 top
C122 "GRM155R71C473KA01D" 0402L 2845,1030 r0 top
C123 "GRM155R71C104KA88D" 0402L 2924,1017 r270 bottom
C124 "GRM188R61E475KE11D" 0603L 3060,1417 r0 bottom
C125 "GRM188R61E475KE11D" 0603L 2783,1015 r270 bottom
C126 "GRM155R71C104KA88D" 0402L 2732,1443 r90 bottom
C127 "GRM155R71C104KA88D" 0402L 2517,1221 r90 bottom
C128 "GRM188R61E475KE11D" 0603L 2993,1325 r0 bottom
C129 "GRM155R71C104KA88D" 0402L 2983,1277 r0 bottom
C130 "GRM155R71C104KA88D" 0402L 2982,1161 r0 bottom
C131 "GRM155R71C104KA88D" 0402L 2830,1026 r270 bottom
C132 "GRM155R71C104KA88D" 0402L 2517,1297 r270 bottom
C133 "GRM155R71C104KA88D" 0402L 2839,1437 r90 bottom
C134 "GRM155R71C104KA88D" 0402L 3051,1464 r0 bottom
C135 "GRM188R61E475KE11D" 0603L 2976.06,1107.41 r0 bottom
C136 "GRM155R71C104KA88D" 0402L 2760,868 r0 bottom
C137 "GRM188R61E475KE11D" 0603L 2762,922 r0 bottom
C138 "GRM188R61E475KE11D" 0603L 2877,1014 r270 bottom
C139 "JMK212BJ226KG-T" 0805L 2736,842 r0 top
C140 "GRM188R61E475KE11D" 0603L 2520,1385 r90 bottom
C141 "GRM155R71C104KA88D" 0402L 2720,1054 r180 bottom
C142 "GRM155R71C104KA88D" 0402L 2574,1205 r180 bottom
C143 "GRM188R61E475KE11D" 0603L 2515,1130 r270 bottom
C144 "GRM155R71C104KA88D" 0402L 2446,1452 r270 bottom
C145 "GRM188R61E475KE11D" 0603L 2372,1445 r0 bottom
C146 "GRM155R71C104KA88D" 0402L 2402,1635 r90 bottom
C147 "GRM188R61E475KE11D" 0603L 2456,1646 r90 bottom
C148 "GRM188R72A104KA35D" 0603L 1812,1996 r0 bottom
C149 "GRM188R72A104KA35D" 0603L 1793,1755 r0 bottom
C150 "GRM21BR61C106KE15L" 0805L 1546,1981 r180 bottom
C151 "GRM155R71C104KA88D" 0402L 1403,1872 r0 top
C152 "GRM155R71C104KA88D" 0402L 1403,1909 r0 top
C153 "GRM155R71C104KA88D" 0402L 1190,1679.21 r270 top
C154 "GRM155R71C473KA01D" 0402L 1255,1700 r180 top
C155 "GRM155R71C104KA88D" 0402L 983,1938 r180 top
C156 "GRM155R71C104KA88D" 0402L 917,1954 r270 top
C157 "GRM188R61E475KE11D" 0603L 1013,2088 r90 top
C158 "GRM155R71C104KA88D" 0402L 1157,2095 r90 bottom
C159 "GRM155R71C104KA88D" 0402L 1137,1728 r180 bottom
C160 "GRM155R71C104KA88D" 0402L 986,1890 r180 top
C161 "GRM155R71C104KA88D" 0402L 919,1872 r90 top
C162 "GRM188R61E475KE11D" 0603L 934,1798 r180 top
C163 "GRM155R71C104KA88D" 0402L 1400,1840 r0 bottom
C164 "GRM155R71C104KA88D" 0402L 1346,1710 r270 bottom
C165 "GRM155R71C104KA88D" 0402L 1251,1709 r270 bottom
C166 "GRM188R61E475KE11D" 0603L 1202,1677 r270 bottom
C167 "GRM188R61E475KE11D" 0603L 1412,1791 r0 bottom
C168 "GRM188R61E475KE11D" 0603L 1299,1697 r270 bottom
C169 "GRM155R71C104KA88D" 0402L 1113,1670 r90 bottom
C170 "GRM188R61E475KE11D" 0603L 1007,1670 r90 top
C171 "JMK212BJ226KG-T" 0805L 2050,1279 r180 bottom
C172 "GRM188R61E475KE11D" 0603L 1435,2004 r0 bottom
C173 "GRM155R71C104KA88D" 0402L 1492,2147 r0 bottom
C174 "GRM188R61E475KE11D" 0603L 1494,2099 r0 bottom
C175 "GRM155R71C104KA88D" 0402L 1421,1956 r0 bottom
C176 "GRM155R71C104KA88D" 0402L 3886,1437 r180 bottom
C177 "GRM188R61E475KE11D" 0603L 3819,1469 r270 bottom
C178 "GRM155R71C104KA88D" 0402L 3945,1643 r90 bottom
C179 "GRM188R61E475KE11D" 0603L 3999,1656 r90 bottom
C180 "GRM188R72A104KA35D" 0603L 3381.57,2001.11 r0 bottom
C181 "GRM188R72A104KA35D" 0603L 3376,1761 r0 bottom
C182 "GRM21BR61C106KE15L" 0805L 3105,1965 r180 bottom
C183 "GRM155R71C104KA88D" 0402L 2980,1851 r0 top
C184 "GRM155R71C104KA88D" 0402L 2980,1889 r0 top
C185 "GRM155R71C104KA88D" 0402L 2778.21,1660.21 r270 top
C186 "GRM155R71C104KA88D" 0402L 2853,2101 r90 bottom
C187 "GRM155R71C104KA88D" 0402L 2513,1940 r270 bottom
C188 "GRM188R61E475KE11D" 0603L 2495,2025 r90 bottom
C189 "GRM155R71C104KA88D" 0402L 2700,1751 r180 bottom
C190 "GRM155R71C104KA88D" 0402L 2573,1879 r180 bottom
C191 "GRM155R71C104KA88D" 0402L 2705,2064 r180 bottom
C192 "GRM155R71C104KA88D" 0402L 2513,1865 r90 bottom
C193 "GRM188R61E475KE11D" 0603L 2517,1776 r270 bottom
C194 "GRM155R71C104KA88D" 0402L 2904,1820 r180 bottom
C195 "GRM155R71C104KA88D" 0402L 2912,1705 r270 bottom
C196 "GRM155R71C104KA88D" 0402L 2819,1703 r270 bottom
C197 "GRM188R61E475KE11D" 0603L 2950,1774 r0 bottom
C198 "GRM188R61E475KE11D" 0603L 2865,1692 r270 bottom
C199 "GRM188R61E475KE11D" 0603L 2772,1672 r270 bottom
C200 "GRM155R71C104KA88D" 0402L 2688,1685 r90 bottom
C201 "GRM188R61E475KE11D" 0603L 2761,1595 r0 bottom
C202 "JMK212BJ226KG-T" 0805L 2732,1535 r0 top
C203 "GRM188R61E475KE11D" 0603L 2995,1994 r0 bottom
C204 "GRM155R71C104KA88D" 0402L 3054,2144 r0 bottom
C205 "GRM188R61E475KE11D" 0603L 3051,2098 r0 bottom
C206 "GRM155R71C104KA88D" 0402L 2981,1947 r0 bottom
C207 "GRM155R71C473KA01D" 0402L 2840,1690 r0 top
C208 "GRM155R71C104KA88D" 0402L 989,569 r180 top
C209 "GRM155R71C104KA88D" 0402L 2834,760 r90 bottom
C210 "GRM155R71C104KA88D" 0402L 984,1254 r180 top
C211 "GRM155R71C104KA88D" 0402L 2574,1260 r180 bottom
C212 "GRM155R71C104KA88D" 0402L 1286,2090 r90 bottom
C213 "GRM155R71C104KA88D" 0402L 2572,1919 r180 bottom
CN1 "ASP-127797-01" ASP-127797-01 773.27,1357.17 r270 bottom locked
CN2 "STD" "3X6 Header 100 MIL PITCH" 293,1336 r0 top
CN3 "STD" "3X6 Header 100 MIL PITCH" 293,735 r0 top
CN4 "STD" "3X6 Header 100 MIL PITCH" 293,1935 r0 top
CN5 "59S10H-40ML5-Y" 59S10H-40ML5-Y 2295,520 r0 top
CN6 "D4S10A-400L5-Z" D4S10A-400L5-Z 1798,510 r90 top
CN7 "59S10H-40ML5-Y" 59S10H-40ML5-Y 3883,520 r0 top
CN8 "D4S10A-400L5-Z" D4S10A-400L5-Z 3384,510 r90 top
CN9 "59S10H-40ML5-Y" 59S10H-40ML5-Y 2295,1202 r0 top
CN10 "D4S10A-400L5-Z" D4S10A-400L5-Z 1798,1192 r90 top
CN11 "59S10H-40ML5-Y" 59S10H-40ML5-Y 3883,1202 r0 top
CN12 "D4S10A-400L5-Z" D4S10A-400L5-Z 3384,1192 r90 top
CN13 "59S10H-40ML5-Y" 59S10H-40ML5-Y 2295,1881.97 r0 top
CN14 "D4S10A-400L5-Z" D4S10A-400L5-Z 1798.27,1872.13 r90 top
CN15 "59S10H-40ML5-Y" 59S10H-40ML5-Y 3883.54,1880 r0 top
CN16 "D4S10A-400L5-Z" D4S10A-400L5-Z 3379.61,1872.1 r90 top
D1 "6CWQ04FNPBF" DPAK 1811,2455.86 r270 top
FID1 "Fiducial" Fiducial10-20 3281,2644 r0 top
FID2 "Fiducial" Fiducial10-20 3543,87 r0 top
FID3 "Fiducial" Fiducial10-20 159,162 r0 top
FID4 "Fiducial" Fiducial10-20 3543,87 r90 bottom
FID5 "Fiducial" Fiducial10-20 3281,2644 r90 bottom
FID6 "Fiducial" Fiducial10-20 159,162 r90 bottom
L1 "SDR2207-4R7ML" SDR2207 2414.41,2389.84 r0 top
L2 "B82442A1222K" B82442A1222K 3575.11,2280.64 r90 top
L3 "B82442A1222K" B82442A1222K 3925.5,2274.73 r90 top
L4 "1008PS-103KLB" 1008PS-103KLB 1709,756 r180 bottom
L5 "1008PS-103KLB" 1008PS-103KLB 1721,267 r180 bottom
L6 "DLW21HN670SQ2L" DLW21HN670SQ2L 1589,526 r180 bottom
L7 "BLM18AG102SN1D" 0603L 2421,188 r90 bottom
L8 "1008PS-472KLB" 1008PS-472KLB 2304,291 r270 bottom
L9 "MSS7341T-104MLB" MSS7341T-104MLB 2414,163 r90 top
L10 "BLM15AX102SN1D" 0402L 989,606 r180 top
L11 "BLM15AX102SN1D" 0402L 989,494 r180 top
L12 "BLM15AX102SN1D" 0402L 1152,310 r270 bottom
L13 "BLM15AX102SN1D" 0402L 1434,683 r0 bottom
L14 "1008PS-103KLB" 1008PS-103KLB 3302,755 r180 bottom
L15 "1008PS-103KLB" 1008PS-103KLB 3300,271 r180 bottom
L16 "DLW21HN670SQ2L" DLW21HN670SQ2L 3175,531 r180 bottom
L17 "BLM18AG102SN1D" 0603L 3936,179 r90 bottom
L18 "1008PS-472KLB" 1008PS-472KLB 3778,285 r270 bottom
L19 "MSS7341T-104MLB" MSS7341T-104MLB 3796,171 r90 top
L20 "BLM15AX102SN1D" 0402L 2576,618 r180 bottom
L21 "BLM15AX102SN1D" 0402L 2575,498 r180 bottom
L22 "BLM15AX102SN1D" 0402L 2732,307 r270 bottom
L23 "BLM15AX102SN1D" 0402L 3007,692 r0 bottom
L24 "1008PS-103KLB" 1008PS-103KLB 1713,1434 r180 bottom
L25 "1008PS-103KLB" 1008PS-103KLB 1704,947 r180 bottom
L26 "DLW21HN670SQ2L" DLW21HN670SQ2L 1585,1210 r180 bottom
L27 "BLM18AG102SN1D" 0603L 2422,863 r90 bottom
L28 "1008PS-472KLB" 1008PS-472KLB 2299,975 r270 bottom
L29 "MSS7341T-104MLB" MSS7341T-104MLB 2410,862 r90 top
L30 "BLM15AX102SN1D" 0402L 986,1291 r180 top
L31 "BLM15AX102SN1D" 0402L 982,1168 r180 top
L32 "BLM15AX102SN1D" 0402L 1152,994 r270 bottom
L33 "BLM15AX102SN1D" 0402L 1431,1367 r0 bottom
L34 "1008PS-103KLB" 1008PS-103KLB 3307,1429 r0 bottom
L35 "1008PS-103KLB" 1008PS-103KLB 3290,943 r0 bottom
L36 "DLW21HN670SQ2L" DLW21HN670SQ2L 3169,1216 r180 bottom
L37 "BLM18AG102SN1D" 0603L 3934,849 r90 bottom
L38 "MSS7341T-104MLB" MSS7341T-104MLB 3796,853 r90 top
L39 "1008PS-472KLB" 1008PS-472KLB 3782,958 r270 bottom
L40 "BLM15AX102SN1D" 0402L 2574,1299 r180 bottom
L41 "BLM15AX102SN1D" 0402L 2733,987 r270 bottom
L42 "BLM15AX102SN1D" 0402L 2577,1159 r180 bottom
L43 "BLM15AX102SN1D" 0402L 2991.81,1371.19 r0 bottom
L44 "1008PS-103KLB" 1008PS-103KLB 1702,2135 r0 bottom
L45 "1008PS-103KLB" 1008PS-103KLB 1712,1631 r0 bottom
L46 "DLW21HN670SQ2L" DLW21HN670SQ2L 1589,1891 r180 bottom
L47 "BLM18AG102SN1D" 0603L 2431,1542 r90 bottom
L48 "1008PS-472KLB" 1008PS-472KLB 2294,1652 r270 bottom
L49 "MSS7341T-104MLB" MSS7341T-104MLB 2413,1538 r90 top
L50 "BLM15AX102SN1D" 0402L 983,1976 r180 top
L51 "BLM15AX102SN1D" 0402L 986,1852 r180 top
L52 "BLM15AX102SN1D" 0402L 1154,1670 r270 bottom
L53 "BLM15AX102SN1D" 0402L 1426.22,2051.26 r0 bottom
L54 "1008PS-103KLB" 1008PS-103KLB 3285.12,2115.28 r0 bottom
L55 "1008PS-103KLB" 1008PS-103KLB 3336,1628 r0 bottom
L56 "DLW21HN670SQ2L" DLW21HN670SQ2L 3166,1870 r180 bottom
L57 "BLM18AG102SN1D" 0603L 3926,1508 r90 bottom
L58 "1008PS-472KLB" 1008PS-472KLB 3774,1638 r270 bottom
L59 "MSS7341T-104MLB" MSS7341T-104MLB 3796,1540 r90 top
L60 "BLM15AX102SN1D" 0402L 2572,1957 r180 bottom
L61 "BLM15AX102SN1D" 0402L 2574,1840 r180 bottom
L62 "BLM15AX102SN1D" 0402L 2727,1685 r270 bottom
L63 "BLM15AX102SN1D" 0402L 2997,2041 r0 bottom
LD1 "LTST-C190CKT" LED_LTST-C190_Red 3242,2499 r270 top
Logo1 "Texas Instruments" TI_Symbol_Overlay_Medium 396,236 r0 top
R1 "CRCW04020000Z0ED" 0402L 710,1856 r270 top
R2 "CRCW04021K00FKED" 0402L 1806,67 r180 top
R3 "CRCW040215K0FKED" 0402L 1889,67 r0 top
R4 "CRCW040210K0FKED" 0402L 2050,390 r90 top
R5 "CRCW040210K0FKED" 0402L 298.27,2576.85 r0 top
R6 "CRCW040210K0FKED" 0402L 298.27,2529.61 r180 top
R7 "CRCW040213K0FKED" 0402L 2104,1037 r180 top
R8 "CRCW04023K01FKED" 0402L 2095,1077 r180 top
R9 "CRCW040210K0FKED" 0402L 1766,923 r180 top
R10 "CRCW04024K99FKED" 0402L 2101,1726 r180 top
R11 "CRCW040211K0FKED" 0402L 2102,1766 r180 top
R12 "CRCW040210K0FKED" 0402L 1806,1581 r180 top
R13 "CRCW04021K00FKED" 0402L 1680,2600 r180 bottom
R14 "CRCW06035K90FKEA" 0603#2 1680,2548 r0 bottom
R15 "CRCW040261K9FKED" 0402L 1680,2490 r0 bottom
R16 "CRCW0805270RJNEA" 0805L 3340,2500 r90 top
R17 "CRCW040210K0FKED" 0402L 3564,2628 r180 top
R18 "CRCW040210K0FKED" 0402L 3934,2638 r0 top
R19 "CRCW040210K0FKED" 0402L 3663.69,2497.17 r0 top
R20 "CRCW040210K0FKED" 0402L 3668,2561 r90 top
R21 "CRCW040210K0FKED" 0402L 3988,2485 r0 top
R22 "CRCW040210K0FKED" 0402L 3972,2546 r90 top
R23 "CRCW08050000Z0EA" 0805L 1580,743 r270 bottom
R24 "CRCW08050000Z0EA" 0805L 1592,310 r90 bottom
R25 "CRCW08050000Z0EA" 0805L 2300,436 r90 bottom
R26 "RC0603JR-071KL" 0603L 2196,273 r270 bottom
R27 "RC0603JR-071KL" 0603L 2289,150 r270 bottom
R28 "CRCW040249R9FKED" 0402L 1849,682 r180 bottom
R29 "CRCW040249R9FKED" 0402L 1858,324 r180 bottom
R30 "CRCW040249R9FKED" 0402L 1255,304 r0 top
R31 "ERA-2AEB103X" 0402L 1144,245 r90 top
R32 "CRCW040233R0JNED" 0402L 1152,759 r270 top
R33 "CRCW0402130RJNED" 0402L 1144,316 r90 top
R34 "ERA-2AEB103X" 0402L 1388,320 r90 top
R35 "ERA-2AEB103X" 0402L 1349,320 r90 top
R36 "CRCW040233R0JNED" 0402L 1319,759 r90 top
R37 "CRCW040233R0JNED" 0402L 1278,759 r270 top
R38 "CRCW04020000Z0ED" 0402L 1425,319 r270 top
R39 "CRCW04020000Z0ED" 0402L 1311,320 r270 top
R40 "CRCW0402130RJNED" 0402L 2095,86 r0 top
R41 "CRCW04022K20JNED" 0402L 1195,766 r90 top
R42 "CRCW04022K20JNED" 0402L 1237,758 r90 top
R43 "CRCW04022K20JNED" 0402L 1974,78 r270 top
R44 "ERA-2AEB103X" 0402L 1801,198 r0 top
R45 "CRCW04020000Z0ED" 0402L 1878,237 r180 top
R46 "CRCW04022K20JNED" 0402L 2037,69 r90 top
R47 "ERA-2AEB103X" 0402L 2097,46 r180 top
R48 "CRCW04023K01FKED" 0402L 1878,197 r180 top
R49 "CRCW040211K0FKED" 0402L 1878,157 r180 top
R50 "CRCW08050000Z0EA" 0805L 3167,737 r270 bottom
R51 "CRCW08050000Z0EA" 0805L 3174,373 r90 bottom
R52 "CRCW08050000Z0EA" 0805L 3885,432 r90 bottom
R53 "RC0603JR-071KL" 0603L 3886,311 r270 bottom
R54 "RC0603JR-071KL" 0603L 3740,109 r0 bottom
R55 "CRCW040249R9FKED" 0402L 3440,701 r180 bottom
R56 "CRCW040249R9FKED" 0402L 3450,313 r180 bottom
R57 "CRCW040249R9FKED" 0402L 2862,305 r0 top
R58 "CRCW040233R0JNED" 0402L 2698,750 r0 top
R59 "ERA-2AEB103X" 0402L 2812,209 r90 top
R60 "ERA-2AEB103X" 0402L 2772,209 r90 top
R61 "CRCW040233R0JNED" 0402L 2907,760 r90 top
R62 "CRCW040233R0JNED" 0402L 2867,760 r270 top
R63 "CRCW04020000Z0ED" 0402L 2852,210 r270 top
R64 "CRCW04023K01FKED" 0402L 2732,208 r270 top
R65 "CRCW04022K20JNED" 0402L 2208,215 r0 top
R66 "CRCW04022K20JNED" 0402L 2826,760 r90 top
R67 "CRCW04022K20JNED" 0402L 2208,256 r0 top
R68 "ERA-2AEB103X" 0402L 2820,119 r180 top
R69 "ERA-2AEB103X" 0402L 2650,180 r0 top
R70 "CRCW04022K20JNED" 0402L 2208,298 r180 top
R71 "CRCW04020000Z0ED" 0402L 2194,40 r0 top
R72 "CRCW04023K01FKED" 0402L 2194,79 r0 top
R73 "CRCW040211K0FKED" 0402L 2195,118 r0 top
R74 "CRCW08050000Z0EA" 0805L 1589,1443 r270 bottom
R75 "CRCW08050000Z0EA" 0805L 1585,989 r90 bottom
R76 "CRCW08050000Z0EA" 0805L 2295,1117 r90 bottom
R77 "RC0603JR-071KL" 0603L 2193,950 r270 bottom
R78 "RC0603JR-071KL" 0603L 2283,843 r270 bottom
R79 "CRCW040249R9FKED" 0402L 1874,1376 r180 bottom
R80 "CRCW040249R9FKED" 0402L 1845,1019 r180 bottom
R81 "CRCW040249R9FKED" 0402L 1260,995 r0 top
R82 "CRCW040233R0JNED" 0402L 1152,1432 r270 top
R83 "ERA-2AEB103X" 0402L 1392,1013 r90 top
R84 "ERA-2AEB103X" 0402L 1354,1013 r90 top
R85 "CRCW040233R0JNED" 0402L 1316,1432 r90 top
R86 "CRCW040233R0JNED" 0402L 1274,1433 r270 top
R87 "CRCW04020000Z0ED" 0402L 1431,1013 r270 top
R88 "CRCW040211K0FKED" 0402L 1315,1013 r270 top
R89 "CRCW04022K20JNED" 0402L 1193,1444 r90 top
R90 "CRCW04022K20JNED" 0402L 1234,1432 r90 top
R91 "CRCW04022K20JNED" 0402L 2007,717 r270 top
R92 "ERA-2AEB103X" 0402L 1778,861 r0 top
R93 "ERA-2AEB103X" 0402L 2097,620 r180 top
R94 "CRCW04022K20JNED" 0402L 2056.14,710.71 r90 top
R95 "CRCW04020000Z0ED" 0402L 1854,899 r180 top
R96 "CRCW04023K01FKED" 0402L 1854,860 r180 top
R97 "CRCW040211K0FKED" 0402L 1854,822 r180 top
R98 "CRCW08050000Z0EA" 0805L 3169,1425 r270 bottom
R99 "CRCW08050000Z0EA" 0805L 3156,995 r90 bottom
R100 "RC0603JR-071KL" 0603L 3891,992 r270 bottom
R101 "CRCW08050000Z0EA" 0805L 3882,1116 r90 bottom
R102 "RC0603JR-071KL" 0603L 3744,777 r0 bottom
R103 "CRCW040249R9FKED" 0402L 3452,1381 r180 bottom
R104 "CRCW040249R9FKED" 0402L 3422,1001 r180 bottom
R105 "CRCW040249R9FKED" 0402L 2845,995 r180 top
R106 "CRCW040233R0JNED" 0402L 2691,1432 r0 top
R107 "ERA-2AEB103X" 0402L 2987.65,954.37 r90 top
R108 "ERA-2AEB103X" 0402L 2948.28,954.37 r90 top
R109 "CRCW040233R0JNED" 0402L 2905,1461 r90 top
R110 "CRCW040233R0JNED" 0402L 2865,1461 r270 top
R111 "CRCW04020000Z0ED" 0402L 3027.02,954.37 r270 top
R112 "CRCW0402100KFKED" 0402L 2908.91,954.37 r270 top
R113 "CRCW04022K20JNED" 0402L 2195.91,895.75 r0 top
R114 "CRCW04022K20JNED" 0402L 2825,1448 r90 top
R115 "CRCW04022K20JNED" 0402L 2195.91,935.12 r0 top
R116 "ERA-2AEB103X" 0402L 2878,847 r180 top
R117 "ERA-2AEB103X" 0402L 2644,852 r270 top
R118 "CRCW04022K20JNED" 0402L 2195.91,974.49 r180 top
R119 "CRCW04020000Z0ED" 0402L 2193,733 r0 top
R120 "CRCW04023K01FKED" 0402L 2193,774 r0 top
R121 "CRCW040211K0FKED" 0402L 2193,814 r0 top
R122 "CRCW08050000Z0EA" 0805L 1582,2093 r270 bottom
R123 "CRCW08050000Z0EA" 0805L 1587,1669 r90 bottom
R124 "CRCW08050000Z0EA" 0805L 2294,1798 r90 bottom
R125 "RC0603JR-071KL" 0603L 2181,1657 r270 bottom
R126 "RC0603JR-071KL" 0603L 2290,1503 r270 bottom
R127 "CRCW040249R9FKED" 0402L 1859,2047 r180 bottom
R128 "CRCW040249R9FKED" 0402L 1846,1687 r180 bottom
R129 "CRCW040249R9FKED" 0402L 1255,1660 r0 top
R130 "CRCW040233R0JNED" 0402L 1135,2102 r0 top
R131 "ERA-2AEB103X" 0402L 1389,1679 r90 top
R132 "ERA-2AEB103X" 0402L 1349,1679 r90 top
R133 "CRCW040233R0JNED" 0402L 1320,2116 r90 top
R134 "CRCW040233R0JNED" 0402L 1280,2116 r270 top
R135 "CRCW04023K01FKED" 0402L 1429,1679 r270 top
R136 "CRCW04020000Z0ED" 0402L 1310,1679 r270 top
R137 "CRCW04022K20JNED" 0402L 1198,2139 r90 top
R138 "CRCW04022K20JNED" 0402L 1240,2116 r90 top
R139 "CRCW04022K20JNED" 0402L 2016.77,1401.65 r270 top
R140 "ERA-2AEB103X" 0402L 1806,1536 r0 top
R141 "ERA-2AEB103X" 0402L 2081,1333 r180 top
R142 "CRCW04022K20JNED" 0402L 2058.11,1401.65 r90 top
R143 "CRCW04020000Z0ED" 0402L 1882.91,1572.91 r180 top
R144 "CRCW04023K01FKED" 0402L 1882.91,1533.54 r180 top
R145 "CRCW040211K0FKED" 0402L 1882.91,1494.17 r180 top
R146 "CRCW08050000Z0EA" 0805L 3162,2071 r270 bottom
R147 "CRCW08050000Z0EA" 0805L 3205,1615 r90 bottom
R148 "CRCW08050000Z0EA" 0805L 3881,1793 r90 bottom
R149 "RC0603JR-071KL" 0603L 3886,1665 r270 bottom
R150 "RC0603JR-071KL" 0603L 3735,1445 r0 bottom
R151 "CRCW040249R9FKED" 0402L 3434,2055 r180 bottom
R152 "CRCW040249R9FKED" 0402L 3455,1685 r180 bottom
R153 "CRCW040249R9FKED" 0402L 2840,1650 r0 top
R154 "CRCW040233R0JNED" 0402L 2520,2011 r45 top
R155 "ERA-2AEB103X" 0402L 2986,1616 r90 top
R156 "ERA-2AEB103X" 0402L 2948,1616 r90 top
R157 "CRCW040233R0JNED" 0402L 2917,2013 r270 bottom
R158 "CRCW040233R0JNED" 0402L 2877,2013 r90 bottom
R159 "CRCW04023K01FKED" 0402L 3022,1616 r270 top
R160 "CRCW040211K0FKED" 0402L 2910,1616 r270 top
R161 "CRCW04022K20JNED" 0402L 2199,1583 r0 top
R162 "CRCW04022K20JNED" 0402L 2795,2107 r180 bottom
R163 "CRCW04022K20JNED" 0402L 2199,1620 r0 top
R164 "ERA-2AEB103X" 0402L 2839,1537 r180 top
R165 "ERA-2AEB103X" 0402L 2641,1533 r270 top
R166 "CRCW04022K20JNED" 0402L 2199,1657 r180 top
R167 "CRCW04020000Z0ED" 0402L 2198,1424 r0 top
R168 "CRCW04023K01FKED" 0402L 2198,1464 r0 top
R169 "CRCW040211K0FKED" 0402L 2198,1502 r0 top
R170 "CRCW0402130RJNED" 0402L 2650,142 r0 top
R171 "CRCW0402130RJNED" 0402L 2657,333 r90 top
R172 "ERA-2AEB103X" 0402L 2656,250 r90 top
R173 "CRCW0402130RJNED" 0402L 2099.45,708.74 r270 top
R174 "CRCW0402130RJNED" 0402L 1142.76,998.11 r90 top
R175 "ERA-2AEB103X" 0402L 1144.72,921.34 r90 top
R176 "CRCW0402130RJNED" 0402L 2631,792 r0 top
R177 "CRCW0402130RJNED" 0402L 2658,1016 r90 top
R178 "ERA-2AEB103X" 0402L 2656,929 r90 top
R179 "CRCW0402130RJNED" 0402L 2099.45,1401.65 r270 top
R180 "CRCW0402130RJNED" 0402L 1128.98,1679.21 r90 top
R181 "ERA-2AEB103X" 0402L 1130,1604 r90 top
R182 "CRCW0402130RJNED" 0402L 2692,1472 r0 top
R183 "CRCW0402130RJNED" 0402L 2690,1703 r90 top
R184 "ERA-2AEB103X" 0402L 2690,1633 r90 top
R185 "CRCW040233R0JNED" 0402L 2103,532.5 r90 bottom
R186 "CRCW040233R0JNED" 0402L 2063,533 r90 bottom
R187 "CRCW040233R0JNED" 0402L 2014,1002 r90 top
R188 "CRCW040233R0JNED" 0402L 2051,1007 r90 top
R189 "CRCW040233R0JNED" 0402L 2035,1697 r90 bottom
R190 "CRCW040233R0JNED" 0402L 2027,1704 r90 top
TP1 "STD" TP-032_RND 1496,248 r0 top
TP2 "STD" TP-032_RND 1499,310 r0 top
TP3 "STD" TP-032_RND 1377,769 r0 top
TP4 "STD" TP-032_RND 1377,712 r0 top
TP5 "STD" TP-032_RND 2963,381 r0 top
TP6 "STD" TP-032_RND 3021,380 r0 top
TP7 "STD" TP-032_RND 2963,799 r0 top
TP8 "STD" TP-032_RND 2964,740 r0 top
TP9 "STD" TP-032_RND 1510,935 r90 top
TP10 "STD" TP-032_RND 1507,989 r90 top
TP11 "STD" TP-032_RND 1374,1466 r0 top
TP12 "STD" TP-032_RND 1374,1410 r0 top
TP13 "STD" TP-032_RND 2972.13,1032.61 r0 top
TP14 "STD" TP-032_RND 3031.18,1032.61 r0 top
TP15 "STD" TP-032_RND 2960.32,1477.49 r0 top
TP16 "STD" TP-032_RND 2960.32,1422.37 r0 top
TP17 "STD" TP-032_RND 1506.93,1606.38 r0 top
TP18 "STD" TP-032_RND 1504.96,1669.37 r0 top
TP19 "STD" TP-032_RND 1386.85,2157.56 r0 top
TP20 "STD" TP-032_RND 1386.85,2100.47 r0 top
TP21 "STD" TP-032_RND 2975.06,1689.74 r0 top
TP22 "STD" TP-032_RND 3041.02,1709.77 r0 top
TP23 "STD" TP-032_RND 2954,2143 r0 top
TP24 "STD" TP-032_RND 2956,2084 r0 top
TR1 "TPD2E001DRLR" DRL0005A 1486,529 r270 bottom
TR2 "TPD2E001DRLR" DRL0005A 3068,531 r270 bottom
TR3 "TPD2E001DRLR" DRL0005A 1482,1208 r270 bottom
TR4 "TPD2E001DRLR" DRL0005A 3066,1216 r270 bottom
TR5 "TPD2E001DRLR" DRL0005A 1486,1891 r270 bottom
TR6 "TPD2E001DRLR" DRL0005A 3062,1870 r270 bottom
U1 "MCP23018-E/MJ" MCP23018-E/MJ 2054,214 r0 top
U2 "LTC1694-1IS5#TRMPBF" LTC1694-1IS5#TRMPBF 156.54,2504.02 r0 top
U3 "AT24C02BN-SH-B" AT24C02BN-SH-B 489.21,2502.05 r0 top
U4 "MCP23018-E/MJ" MCP23018-E/MJ 2030.55,858.35 r0 top
U5 "MCP23018-E/MJ" MCP23018-E/MJ 2048.27,1559.13 r0 top
U6 "LM22677TJ-ADJ/NOPB" TJ7A_N 1288,2482 r180 top
U7 "LM3676SD-1.8/NOPB" SDA08A 3553.16,2536.88 r90 top
U8 "LM3676SD-1.8/NOPB" SDA08A 3884.16,2535.88 r90 top
U9 "DS90UB914ATRHSTQ1" RHS0048A 1194,548 r270 top
U10 "DS90UB914ATRHSTQ1" RHS0048A 2770,551 r270 top
U11 "DS90UB914ATRHSTQ1" RHS0048A 1194,1230 r270 top
U12 "DS90UB914ATRHSTQ1" RHS0048A 2770,1233 r270 top
U13 "DS90UB914ATRHSTQ1" RHS0048A 1190,1909.53 r270 top
U14 "DS90UB914ATRHSTQ1" RHS0048A 2769,1890.53 r270 top
ZZ2 "These assemblies are ESD sensitive, ESD precautions shall be observed." AssemblyNote 163,3141.11 r0 top
ZZ3 "These assemblies must be clean and free from flux and all contaminants. Use of no clean flux is not acceptable." AssemblyNote 163,3052.56 r0 top
ZZ4 "These assemblies must comply with workmanship standards IPC-A-610 Class 2, unless otherwise specified." AssemblyNote 163,2964 r0 top

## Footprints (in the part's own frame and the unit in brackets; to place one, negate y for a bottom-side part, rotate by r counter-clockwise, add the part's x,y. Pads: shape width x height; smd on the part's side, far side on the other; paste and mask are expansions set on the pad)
"3X6 Header 100 MIL PITCH" [mil]
  rect 60x60 hole 35.43: 1(100,-252) 7(0,-252) 13(-100,-252)
  round 60 hole 35.43: 2(100,-152) 3(100,-52) 4(100,48) 5(100,148) 6(100,248) 8(0,-152) 9(0,-52) 10(0,48) 11(0,148) 12(0,248) 14(-100,-152) 15(-100,-52) 16(-100,48) 17(-100,148) 18(-100,248)
  silkscreen extent -150,-302 150,298
59S10H-40ML5-Y [mm] "Rosenberger Straight Plug"
  round 1.3 hole 0.9: 1(0,0)
  round 1.8 hole 1.4: 2(-2.54,2.54) 3(-2.54,-2.54) 4(2.54,-2.54) 5(2.54,2.54)
  silkscreen extent -3.75,-3.81 4.44,3.81
0402L [mm] "0402 from SM-752 data"
  rect 0.6x0.5 smd: 1(-0.5,0) 2(0.5,0)
  body extent -0.55,-0.3 0.55,0.3, height 0.6
0603#1 [mil]
  rect 30x32 smd mask+2: 1(-31,0) 2(31,0)
  silkscreen extent -38,-23 38,23, body extent -34,-19 34,19, height 33
0603#2 [mil] "0603 from SM-752 data"
  rect 39.37x37.4 smd: 1(-31.5,0) 2(31.5,0)
  silkscreen extent -60,-27 60,27, body extent -34,-19 34,19, height 33
0603L [mm] "0603 from SM-752 data"
  rect 0.8x0.85 smd: 1(-0.7,0) 2(0.7,0)
  silkscreen extent -0.07,-0.33 0.07,0.33, body extent -0.87,-0.47 0.87,0.47, height 0.85
0805L [mm] "0805 from SM-752 data"
  rect 1.1x1.4 smd: 1(-0.75,0) 2(0.75,0)
  body extent -1.1,-0.72 1.1,0.72, height 1.1
1008PS-103KLB [mm] "Coilcraft Inductor"
  rect 1.02x2.54 smd: 1(-1.143,0) 2(1.143,0)
  silkscreen extent -2,-2 2,2, body extent -1.9,-1.9 1.91,1.91, height 2.74
1008PS-472KLB [mil] "Coilcraft Inductor"
  rect 40.16x100 smd: 1(-45,0) 2(45,0)
  silkscreen extent -79,-79 79,79, body extent -75,-75 75,75, height 108
1206L [mm] "1206 from SM-752 data"
  rect 1.1x1.75 smd: 1(-1.35,0) 2(1.35,0)
  silkscreen extent -0.4,-0.77 0.4,0.77, body extent -1.7,-0.9 1.7,0.9, height 1.35
ASP-127797-01 [mm]
  round 0.64 smd: 1(24.765,3.175) 2(23.495,3.175) 3(22.225,3.175) 4(20.955,3.175) 5(19.685,3.175) 6(18.415,3.175) 7(17.145,3.175) 8(15.875,3.175) 9(14.605,3.175) 10(13.335,3.175) 11(12.065,3.175) 12(10.795,3.175) 13(9.525,3.175) 14(8.255,3.175) 15(6.985,3.175) 16(5.715,3.175) 17(4.445,3.175) 18(3.175,3.175) 19(1.905,3.175) 20(0.635,3.175) 21(-0.635,3.175) 22(-1.905,3.175) 23(-3.175,3.175) 24(-4.445,3.175) 25(-5.715,3.175) 26(-6.985,3.175) 27(-8.255,3.175) 28(-9.525,3.175) 29(-10.795,3.175) 30(-12.065,3.175) 31(-13.335,3.175) 32(-14.605,3.175) 33(-15.875,3.175) 34(-17.145,3.175) 35(-18.415,3.175) 36(-19.685,3.175) 37(-20.955,3.175) 38(-22.225,3.175) 39(-23.495,3.175) 40(-24.765,3.175) 41(24.765,1.905) 42(23.495,1.905) 43(22.225,1.905) 44(20.955,1.905) 45(19.685,1.905) 46(18.415,1.905) 47(17.145,1.905) 48(15.875,1.905) 49(14.605,1.905) 50(13.335,1.905) 51(12.065,1.905) 52(10.795,1.905) 53(9.525,1.905) 54(8.255,1.905) 55(6.985,1.905) 56(5.715,1.905) 57(4.445,1.905) 58(3.175,1.905) 59(1.905,1.905) 60(0.635,1.905) 61(-0.635,1.905) 62(-1.905,1.905) 63(-3.175,1.905) 64(-4.445,1.905) 65(-5.715,1.905) 66(-6.985,1.905) 67(-8.255,1.905) 68(-9.525,1.905) 69(-10.795,1.905) 70(-12.065,1.905) 71(-13.335,1.905) 72(-14.605,1.905) 73(-15.875,1.905) 74(-17.145,1.905) 75(-18.415,1.905) 76(-19.685,1.905) 77(-20.955,1.905) 78(-22.225,1.905) 79(-23.495,1.905) 80(-24.765,1.905) 81(24.765,-1.905) 82(23.495,-1.905) 83(22.225,-1.905) 84(20.955,-1.905) 85(19.685,-1.905) 86(18.415,-1.905) 87(17.145,-1.905) 88(15.875,-1.905) 89(14.605,-1.905) 90(13.335,-1.905) 91(12.065,-1.905) 92(10.795,-1.905) 93(9.525,-1.905) 94(8.255,-1.905) 95(6.985,-1.905) 96(5.715,-1.905) 97(4.445,-1.905) 98(3.175,-1.905) 99(1.905,-1.905) 100(0.635,-1.905) 101(-0.635,-1.905) 102(-1.905,-1.905) 103(-3.175,-1.905) 104(-4.445,-1.905) 105(-5.715,-1.905) 106(-6.985,-1.905) 107(-8.255,-1.905) 108(-9.525,-1.905) 109(-10.795,-1.905) 110(-12.065,-1.905) 111(-13.335,-1.905) 112(-14.605,-1.905) 113(-15.875,-1.905) 114(-17.145,-1.905) 115(-18.415,-1.905) 116(-19.685,-1.905) 117(-20.955,-1.905) 118(-22.225,-1.905) 119(-23.495,-1.905) 120(-24.765,-1.905) 121(24.765,-3.175) 122(23.495,-3.175) 123(22.225,-3.175) 124(20.955,-3.175) 125(19.685,-3.175) 126(18.415,-3.175) 127(17.145,-3.175) 128(15.875,-3.175) 129(14.605,-3.175) 130(13.335,-3.175) 131(12.065,-3.175) 132(10.795,-3.175) 133(9.525,-3.175) 134(8.255,-3.175) 135(6.985,-3.175) 136(5.715,-3.175) 137(4.445,-3.175) 138(3.175,-3.175) 139(1.905,-3.175) 140(0.635,-3.175) 141(-0.635,-3.175) 142(-1.905,-3.175) 143(-3.175,-3.175) 144(-4.445,-3.175) 145(-5.715,-3.175) 146(-6.985,-3.175) 147(-8.255,-3.175) 148(-9.525,-3.175) 149(-10.795,-3.175) 150(-12.065,-3.175) 151(-13.335,-3.175) 152(-14.605,-3.175) 153(-15.875,-3.175) 154(-17.145,-3.175) 155(-18.415,-3.175) 156(-19.685,-3.175) 157(-20.955,-3.175) 158(-22.225,-3.175) 159(-23.495,-3.175) 160(-24.765,-3.175)
  round 1.27 hole 1.27 unplated: 161(27.19,0) 162(-27.19,-3.05)
  silkscreen extent -28.14,-7.34 28.78,7.34
AssemblyNote [mil] "Assembly Note"
AT24C02BN-SH-B [mil]
  rect 67x26 smd: 1(-104.79,75.05) 2(-104.79,25.05) 3(-104.79,-24.95) 4(-104.79,-74.95) 5(103.21,-74.95) 6(103.21,-24.95) 7(103.21,25.05) 8(103.21,75.05)
  silkscreen extent -51,-95 49,100
B82442A1222K [mm]
  rect 2x4.5 smd: 1(3.037,-0.001) 2(-2.963,-0.001)
  silkscreen extent -2.91,-2.65 2.99,2.65
CAPSMT_62_F60 [mm] "6.3 x 5.7mm:  Chemi-Con F60"
  rect 3.5x1.6 smd: 1(-2.688,0.012) 2(2.712,0.012)
  silkscreen extent -3.35,-3.39 3.45,3.41, body extent -3.4,-3.4 3.45,3.42, height 6
D4S10A-400L5-Z [mm]
  round 1.3 hole 0.9: 1(-1,1) 2(-1,-1) 3(1,-1) 4(1,1)
  round 2.1 hole 1.7: 5(-3,3) 6(3,3)
  round 1.7 hole 1.3: 7(-3,-3) 8(3,-3)
  silkscreen extent -6,-6 6,8.5
DLW21HN670SQ2L [mil]
  rect 40x22.13 smd paste-1000 mask-1000: 1(-35.98,18.98) 2(36.02,18.98) 3(35.98,-18.94) 4(-35.91,-18.98)
  silkscreen extent -65,-40 65,67
DPAK [mm] "D-PAK, 3-Pads, Body 6.22x6.73mm (max), TO-252AA using nominal STEP model"
  rect 2.6x1.6 smd: 1(-3.4,2.28) 3(-3.4,-2.28)
  rect 6.2x5.8 smd paste-2.9: 4(3.4,0)
  silkscreen extent -5,-3.5 6.83,3.5, body extent -3.86,-3.29 5.84,3.29, height 2.48
DRL0005A [mm] "SOTFL, 5-Flat Leads, Body 1.2x1.6x0.6mm, Pitch 0.5mm, TI Recommended"
  rect 0.45x0.3 smd: 1(-0.675,0.5) 2(-0.675,0) 3(-0.675,-0.5) 4(0.675,-0.5) 5(0.675,0.5)
  silkscreen extent -1,-1 0.55,1.05, body extent -0.65,-0.85 0.65,0.85, height 0.6
Fiducial10-20 [mm]
  round 1 smd paste-0.5 mask+0.5: 1(0,0)
  Top Layer keep-out circle w1.178: c0,0 r0.5
LED_LTST-C190_Red [mm] "Lite-On"
  rect 0.8x0.8 smd: 1(-0.75,0) 2(0.75,0)
  silkscreen extent -1.1,-0.8 1.8,0.8, body extent -0.85,-0.45 0.85,0.45, height 0.9
LTC1694-1IS5#TRMPBF [mm]
  rect 0.6x1.05 smd mask+0: 1(-0.95,-1.35) 2(0,-1.35) 3(0.95,-1.35) 4(0.95,1.35) 5(-0.95,1.35)
  silkscreen extent -1.63,-0.87 1.63,0.87, body extent -1.5,-1.5 1.5,1.5, height 1.45
MCP23018-E/MJ [mm]
  rect 0.85x0.3 smd: 1(1.95,-1.25) 2(1.95,-0.75) 3(1.95,-0.25) 4(1.95,0.25) 5(1.95,0.75) 6(1.95,1.25) 13(-1.95,1.25) 14(-1.95,0.75) 15(-1.95,0.25) 16(-1.95,-0.25) 17(-1.95,-0.75) 18(-1.95,-1.25)
  rect 0.3x0.85 smd: 7(1.25,1.95) 8(0.75,1.95) 9(0.25,1.95) 10(-0.25,1.95) 11(-0.75,1.95) 12(-1.25,1.95) 19(-1.25,-1.95) 20(-0.75,-1.95) 21(-0.25,-1.95) 22(0.25,-1.95) 23(0.75,-1.95) 24(1.25,-1.95)
  rect 2.6x2.6 smd paste-25.4: 25(0,0)
  silkscreen extent -2,-2.18 2.59,2
MSS7341T-104MLB [mm]
  round 0.5 smd mask+0: 1(0,3.2) 2(0,-3.2)
  Top Layer region: -3.55,1.05 -3.55,3.55 3.55,3.55 3.55,1.05 2.623,1.05 1.85,2.135 0.666,2.745 -0.666,2.745 -1.85,2.135 -2.623,1.05 -2.623,1.05
  Top Layer region: -3.55,-3.55 -3.55,-1.05 -2.623,-1.05 -1.85,-2.135 -0.666,-2.745 0.666,-2.745 1.85,-2.135 2.623,-1.05 2.623,-1.05 3.55,-1.05 3.55,-3.55
  silkscreen extent -3.65,-0.8 3.65,0.8, body extent -3.66,-3.56 3.66,3.56, height 4.1
RHS0048A [mm] "QFN, 48-Leads, Body 7x7mm, Pitch 0.5mm, TI Recommended"
  rect 0.6x0.25 smd mask+0.051: 1(-3.4,2.75) 2(-3.4,2.25) 3(-3.4,1.75) 4(-3.4,1.25) 5(-3.4,0.75) 6(-3.4,0.25) 7(-3.4,-0.25) 8(-3.4,-0.75) 9(-3.4,-1.25) 10(-3.4,-1.75) 11(-3.4,-2.25) 12(-3.4,-2.75) 25(3.4,-2.75) 26(3.4,-2.25) 27(3.4,-1.75) 28(3.4,-1.25) 29(3.4,-0.75) 30(3.4,-0.25) 31(3.4,0.25) 32(3.4,0.75) 33(3.4,1.25) 34(3.4,1.75) 35(3.4,2.25) 36(3.4,2.75)
  rect 0.25x0.6 smd mask+0.051: 13(-2.75,-3.4) 14(-2.25,-3.4) 15(-1.75,-3.4) 16(-1.25,-3.4) 17(-0.75,-3.4) 18(-0.25,-3.4) 19(0.25,-3.4) 20(0.75,-3.4) 21(1.25,-3.4) 22(1.75,-3.4) 23(2.25,-3.4) 24(2.75,-3.4) 37(2.75,3.4) 38(2.25,3.4) 39(1.75,3.4) 40(1.25,3.4) 41(0.75,3.4) 42(0.25,3.4) 43(-0.25,3.4) 44(-0.75,3.4) 45(-1.25,3.4) 46(-1.75,3.4) 47(-2.25,3.4) 48(-2.75,3.4)
  rect 5.1x5.1 smd paste-2.55 mask+0.076: 49(0,0)
  silkscreen extent -3.85,3.27 -3.27,3.85, body extent -3.55,-3.55 3.55,3.55, height 0.81
SDA08A [mm] "SON, 8-Leads, Body 3x3mm, Pitch 0.5mm, NSC Recommended"
  rect 0.6x0.25 smd paste-0.125 mask+0.051: 1(-1.4,0.75) 2(-1.4,0.25) 3(-1.4,-0.25) 4(-1.4,-0.75) 5(1.4,-0.75) 6(1.4,-0.25) 7(1.4,0.25) 8(1.4,0.75)
  rect 1.6x2 smd paste-0.05 mask+0.051: 9(0,0)
  silkscreen extent -2,-1.7 1.85,2.39, body extent -1.55,-1.55 1.55,1.55, height 0.8
SDR2207 [mm] "Bourns recommnded land pattern rev 10/08"
  rect 4x9 smd: 1(-8.75,0) 2(8.75,0)
  silkscreen extent -11.2,-7.7 11.2,7.7, body extent -11.15,-7.65 11.15,7.65, height 7.8
TI_Symbol_Overlay_Medium [mil]
  silkscreen extent -124,-122 124,120
TJ7A_N [mm] "D2-PAK, 8-Leads, Body 9.9x10.2mm, Pitch 1.27mm, Lead Span 14mm, IPC Medium Density"
  rect 3.2x0.8 smd: 1(-6,3.81) 2(-6,2.54) 3(-6,1.27) 4(-6,0) 5(-6,-1.27) 6(-6,-2.54) 7(-6,-3.81)
  rect 7.4x5.75 smd: 8(3.9,0)
  silkscreen extent -6.18,-5.2 -0.2,5.2, body extent -1.95,-5.2 8.15,5.2, height 2.1
TP-032_RND [mil]
  round 47 hole 32: 1(0,0)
